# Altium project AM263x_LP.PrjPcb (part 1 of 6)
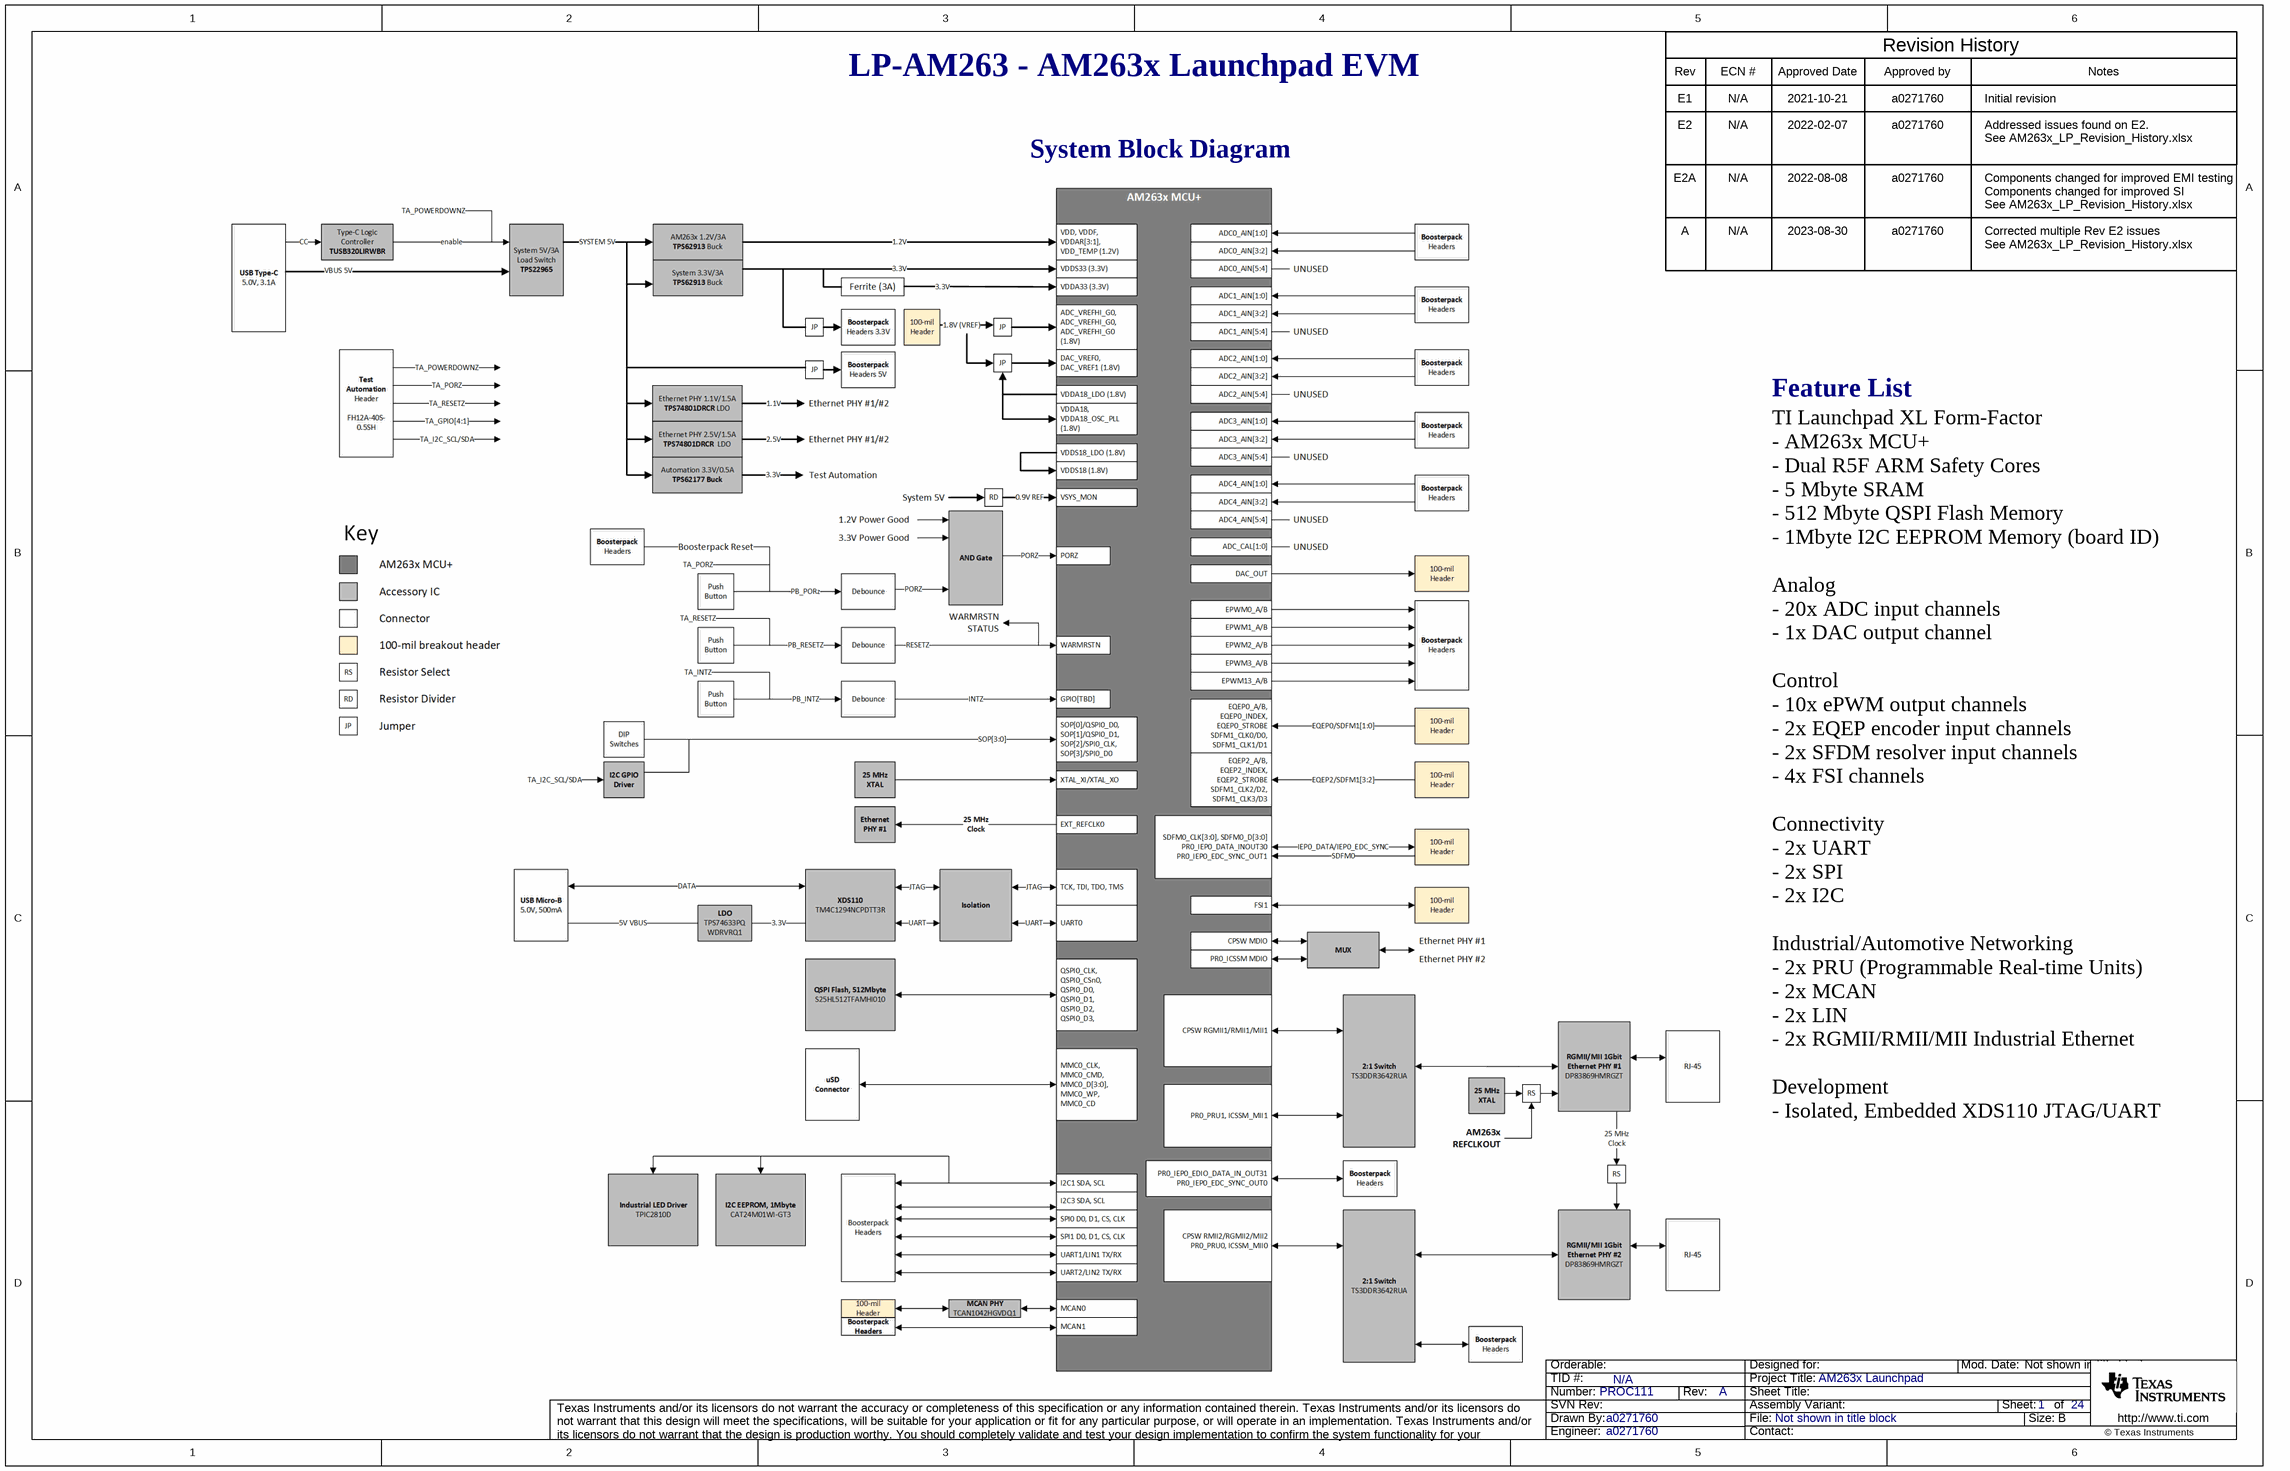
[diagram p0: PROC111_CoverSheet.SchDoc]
DrawnBy: a0271760; PCB_Rev: A; PRJ_Engineer: a0271760; PRJ_Number: PROC111; PRJ_Title: AM263x Launchpad; Sch_Rev: A; TID: N/A
24 sheets, 815 parts. Net scope: global (net labels, ports and power ports of the same name join across sheets).
Board file: PROC111A.PcbDoc
Sheets:
  PROC111_CoverSheet.SchDoc
  PROC111_System_Power_1.SchDoc
  PROC111_System_Power_2.SchDoc
  PROC111_AM263x_1_Power.SchDoc
  PROC111_AM263x_2_Clock_Reset_Boot_JTAG.SchDoc
  PROC111_AM263x_Serial_Connectivity.SchDoc
  PROC111_AM263x_3_QSPI_MMC.SchDoc
  PROC111_AM263x_4_ADC_DAC.SchDoc
  PROC111_AM263x_5_ePWM_eQEP_FSI.SchDoc
  PROC111_AM263x_6_RGMII_MII.SchDoc
  PROC111_AM263x_7_PRU.SchDoc
  PROC111_AM263x_8_SDFM.SchDoc
  PROC111_Push_Buttons.SchDoc
  PROC111_Test_Automation.SchDoc
  PROC111_Ehernet_PHY_1.SchDoc
  PROC111_Ehernet_PHY_2.SchDoc
  PROC111_Ehernet_RJ45_1.SchDoc
  PROC111_Ehernet_RJ45_2.SchDoc
  PROC111_Boosterpack_Headers.SchDoc
  PROC111_Breakout_Headers.SchDoc
  PROC111_XDS110_1.SchDoc
  PROC111_XDS110_2.SchDoc
  PROC111_LED.SchDoc
  PROC111_Hardware.SchDoc

## Sheet PROC111_CoverSheet.SchDoc
size 431 x 279 mm; Date: Not shown in title block; ApprovedBy: Not shown in title block; CheckedBy: Not shown in title block; Author: Not shown in title block; CompanyName: Not shown in title block; Engineer: Not shown in title block; Organization: Not shown in title block; Address1: Not shown in title block; Address2: Not shown in title block; Address3: Not shown in title block; Address4: Not shown in title block; DocumentNumber: 1; Revision: Use project parameter SCH_Rev; SheetNumber: 1; SheetTotal: 24; PageSetup: Record=PageOptions¦CenterHorizontal=True¦CenterVertical=True¦PrintScale=1.00¦XCorrection=1.00¦YCorrection=1.00¦PrintKind=0¦BorderSize=5000000¦LeftOffset=0¦BottomOffset=0¦Orientation=2¦PaperLength=1000¦PaperWidth=1000¦Scale=100¦PaperSource=15¦PrintQuality=600¦MediaType=1¦DitherType=10¦PaperKind=Letter¦PrintScaleMode=1

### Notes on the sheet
- LP-AM263 - AM263x Launchpad EVM
- Rev
- E1
- ECN #
- N/A
- Approved Date
- 2021-10-21
- Approved by
- a0271760
- Revision History
- Initial revision
- Notes
- System Block Diagram
- E2
- 2022-02-07
- Addressed issues found on E2.
- See AM263x_LP_Revision_History.xlsx
- E2A
- A
- 2022-08-08
- 2023-08-30
- Components changed for improved SI
- Components changed for improved EMI testing
- Corrected multiple Rev E2 issues
- Feature List
- TI Launchpad XL Form-Factor
  - AM263x MCU+
  - Dual R5F ARM Safety Cores
  - 5 Mbyte SRAM
  - 512 Mbyte QSPI Flash Memory
  - 1Mbyte I2C EEPROM Memory (board ID)
  Analog
  - 20x ADC input channels
  - 1x DAC output channel
  Control
  - 10x ePWM output channels
  - 2x EQEP encoder input channels
  - 2x SFDM resolver input channels
  - 4x FSI channels
  Connectivity
  - 2x UART
  - 2x SPI
  - 2x I2C
  Industrial/Automotive Networking
  - 2x PRU (Programmable Real-time Units)
  - 2x MCAN
  - 2x LIN
  - 2x RGMII/RMII/MII Industrial Ethernet
  Development
  - Isolated, Embedded XDS110 JTAG/UART

## Sheet PROC111_System_Power_1.SchDoc
size 431 x 279 mm; Date: Not shown in title block; ApprovedBy: Not shown in title block; CheckedBy: Not shown in title block; Author: Not shown in title block; CompanyName: Not shown in title block; Engineer: Not shown in title block; Organization: Not shown in title block; Address1: Not shown in title block; Address2: Not shown in title block; Address3: Not shown in title block; Address4: Not shown in title block; DocumentNumber: 2; Revision: Use project parameter SCH_Rev; SheetNumber: 2; SheetTotal: 24; PageSetup: Record=PageOptions¦CenterHorizontal=True¦CenterVertical=True¦PrintScale=1.00¦XCorrection=1.00¦YCorrection=1.00¦PrintKind=0¦BorderSize=5000000¦LeftOffset=0¦BottomOffset=0¦Orientation=2¦PaperLength=1000¦PaperWidth=1000¦Scale=100¦PaperSource=15¦PrintQuality=600¦MediaType=1¦DitherType=10¦PaperKind=Letter¦PrintScaleMode=1
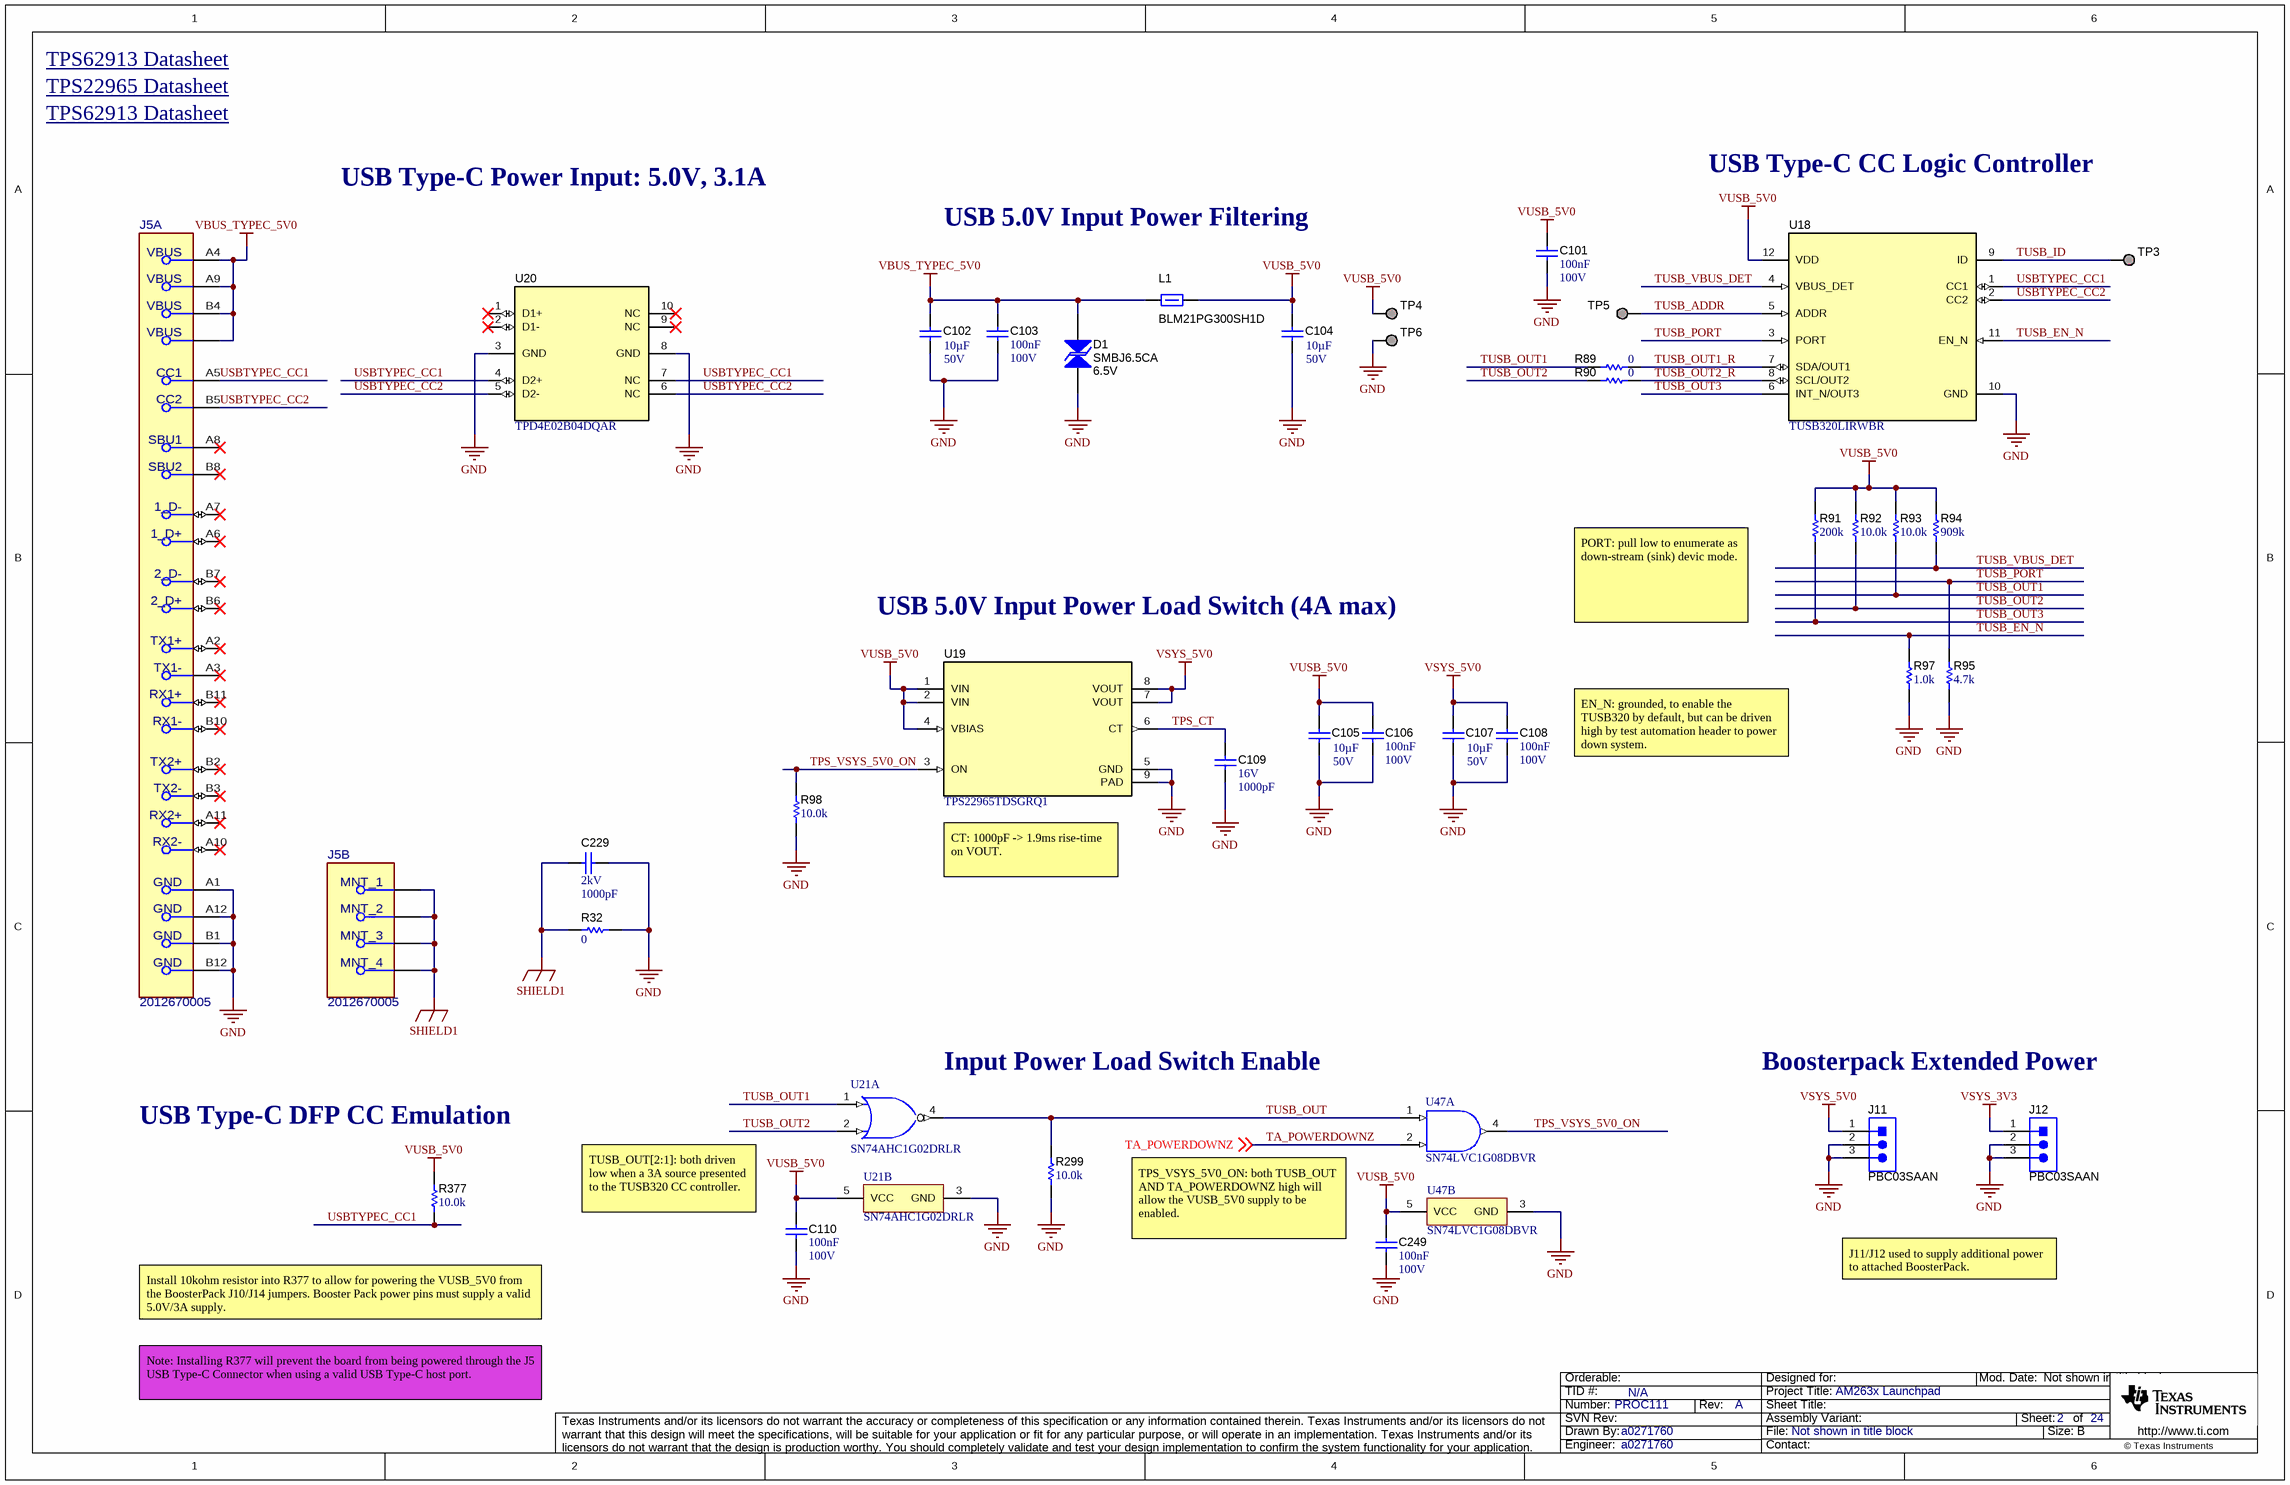
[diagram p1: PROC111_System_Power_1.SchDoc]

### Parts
C101  Cap_F: 100nF  VDC_V: 100V  [0603]  (hidden comment: GRM188R72A104KA35D)
C102  VDC_V: 50V  ValueDisplayed: 10µF  [1210_270]  (hidden comment: CL32A106KBJNNNE)
C103  Cap_F: 100nF  VDC_V: 100V  [0603]  (hidden comment: GRM188R72A104KA35J)
C104  VDC_V: 50V  ValueDisplayed: 10µF  [1210_270]  (hidden comment: CL32A106KBJNNNE)
C105  VDC_V: 50V  ValueDisplayed: 10µF  [1210_270]  (hidden comment: CL32A106KBJNNNE)
C106  Cap_F: 100nF  VDC_V: 100V  [0603]  (hidden comment: GRM188R72A104KA35D)
C107  VDC_V: 50V  ValueDisplayed: 10µF  [1210_270]  (hidden comment: CL32A106KBJNNNE)
C108  Cap_F: 100nF  VDC_V: 100V  [0603]  (hidden comment: GRM188R72A104KA35D)
C109  VDC_V: 16V  ValueDisplayed: 1000pF  [0402]  (hidden comment: GRM155R71C102KA01D)
C110  Cap_F: 100nF  VDC_V: 100V  [0603]  (hidden comment: GRM188R72A104KA35D)
C229  VDC_V: 2kV  ValueDisplayed: 1000pF  [1808]  (hidden comment: GR442QR73D102KW01L)
C249  Cap_F: 100nF  VDC_V: 100V  [0603]  (hidden comment: GRM188R72A104KA35D)
D1  SMBJ6.5CA  value 6.5V  [SMB-Bi]
J5  2012670005  [FP-2012670005_CONN_USB_9MM39_8MM21-MFG]  (parts A,B of 2)
J11  PBC03SAAN  [PBC03SAAN]
J12  PBC03SAAN  [PBC03SAAN]
L1  BLM21PG300SH1D  [0805_HV]
R32  ValueDisplayed: 0  [0805_HV]  (hidden comment: ERJ-6GEY0R00V)
R89  ValueDisplayed: 0  [0402L]  (hidden comment: ERJ-2GE0R00X)
R90  ValueDisplayed: 0  [0402L]  (hidden comment: ERJ-2GE0R00X)
R91  ValueDisplayed: 200k  [0402]  (hidden comment: CRCW0402200KJNED)
R92  ValueDisplayed: 10.0k  [0402]  (hidden comment: ERJ-2RKF1002X)
R93  ValueDisplayed: 10.0k  [0402]  (hidden comment: ERJ-2RKF1002X)
R94  ValueDisplayed: 909k  [0402]  (hidden comment: CRCW0402909KFKED)
R95  ValueDisplayed: 4.7k  [0402]  (hidden comment: CRCW04024K70JNED)
R97  ValueDisplayed: 1.0k  [0402]  (hidden comment: ERJ-2GEJ102X)
R98  ValueDisplayed: 10.0k  [0402]  (hidden comment: ERJ-2RKF1002X)
R299  ValueDisplayed: 10.0k  [0402]  (hidden comment: ERJ-2RKF1002X)
R377  ValueDisplayed: 10.0k  [0402]  (hidden comment: ERJ-2RKF1002X)
TP3  TESTPOINT  [TP_25MIL-SMT]  (value not drawn)  (no BOM)
TP4  TESTPOINT  [TP_25MIL-SMT]  (value not drawn)  (no BOM)
TP5  TESTPOINT  [TP_25MIL-SMT]  (value not drawn)  (no BOM)
TP6  TESTPOINT  [TP_25MIL-SMT]  (value not drawn)  (no BOM)
U18  TUSB320LIRWBR  [RWB0012A]
U19  TPS22965TDSGRQ1  [DSG0008B]
U20  TPD4E02B04DQAR  [DQA0010A]
U21  SN74AHC1G02DRLR  [DRL0005A]  (parts A,B of 2)
U47  SN74LVC1G08DBVR  [DBV0005A_N]  (parts A,B of 2)

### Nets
GND: C101.2 C102.2 C103.2 C104.2 C105.2 C106.2 C107.2 C108.2 C109.2 C110.2 C229.1 C249.2 D1.1 J5.A1(GND) J5.A12(GND) J5.B1(GND) J5.B12(GND) J11.2 J11.3 J12.2 J12.3 R32.2 R95.1 R97.1 R98.2 R299.2 TP6.1 U18.10(GND) U19.5(GND) U19.9(PAD) U20.3(GND) U20.8(GND) U21.3(GND) U47.3(GND)
SHIELD1: C229.2 J5.1(MNT_1) J5.2(MNT_2) J5.3(MNT_3) J5.4(MNT_4) R32.1
VBUS_TYPEC_5V0: C102.1 C103.1 D1.2 J5.A4(VBUS) J5.A9(VBUS) J5.B4(VBUS) J5.B9(VBUS) L1.1
VSYS_3V3: J12.1
VSYS_5V0: C107.1 C108.1 J11.1 U19.7(VOUT) U19.8(VOUT)
VUSB_5V0: C101.1 C104.1 C105.1 C106.1 C110.1 C249.1 L1.2 R91.2 R92.1 R93.1 R94.2 R377.1 TP4.1 U18.12(VDD) U19.1(VIN) U19.2(VIN) U19.4(VBIAS) U21.5(VCC) U47.5(VCC)
TA_POWERDOWNZ: U47.2(B) ; off-sheet TA_POWERDOWNZ
TPS_CT: C109.1 U19.6(CT)
TPS_VSYS_5V0_ON: R98.1 U19.3(ON) U47.4(Y)
TUSB_ADDR: TP5.1 U18.5(ADDR)
TUSB_EN_N: R97.2 U18.11(EN_N)
TUSB_ID: TP3.1 U18.9(ID)
TUSB_OUT: R299.1 U21.4(Y) U47.1(A)
TUSB_OUT1: R89.2 R93.2 U21.1(A)
TUSB_OUT1_R: R89.1 U18.7(SDA/OUT1)
TUSB_OUT2: R90.2 R92.2 U21.2(B)
TUSB_OUT2_R: R90.1 U18.8(SCL/OUT2)
TUSB_OUT3: R91.1 U18.6(INT_N/OUT3)
TUSB_PORT: R95.2 U18.3(PORT)
TUSB_VBUS_DET: R94.1 U18.4(VBUS_DET)
USBTYPEC_CC1: J5.A5(CC1) R377.2 U18.1(CC1) U20.4(D2+) U20.7(NC)
USBTYPEC_CC2: J5.B5(CC2) U18.2(CC2) U20.5(D2-) U20.6(NC)

Not connected (* = marked no-connect by the designer): J5 A2(TX1+)* A3(TX1-)* A6(1_D+)* A7(1_D-)* A8(SBU1)* A10(RX2-)* A11(RX2+)* B2(TX2+)* B3(TX2-)* B6(2_D+)* B7(2_D-)* B8(SBU2)* B10(RX1-)* B11(RX1+)*; U20 1(D1+)* 2(D1-)* 9(NC)* 10(NC)*

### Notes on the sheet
- TPS62913 Datasheet <https://www.ti.com/product/TPS62913>
- TPS22965 Datasheet <http://www.ti.com/lit/ds/symlink/tps22965-q1.pdf>
- TPS62913 Datasheet <datasheets/IC-TPS62913RPUR.pdf>
- USB Type-C Power Input: 5.0V, 3.1A
- USB 5.0V Input Power Filtering
- USB Type-C CC Logic Controller
- USB 5.0V Input Power Load Switch (4A max)
- PORT: pull low to enumerate as down-stream (sink) devic mode.
- EN_N: grounded, to enable the TUSB320 by default, but can be driven high by test automation header to power down system.
  TA_POWERDOWNZ: pulled high by default. Can be driven low by TA Header to disable USB 5.0V supply.
- (near U19) CT: 1000pF -> 1.9ms rise-time on VOUT.
- (near U21) Input Power Load Switch Enable
- Boosterpack Extended Power
- USB Type-C DFP CC Emulation
- (near C110) TUSB_OUT[2:1]: both driven low when a 3A source presented to the TUSB320 CC controller.
- (near C249) TPS_VSYS_5V0_ON: both TUSB_OUT AND TA_POWERDOWNZ high will allow the VUSB_5V0 supply to be enabled.
- J11/J12 used to supply additional power to attached BoosterPack.
- Install 10kohm resistor into R377 to allow for powering the VUSB_5V0 from the BoosterPack J10/J14 jumpers. Booster Pack power pins must supply a valid 5.0V/3A supply.
- Note: Installing R377 will prevent the board from being powered through the J5 USB Type-C Connector when using a valid USB Type-C host port.

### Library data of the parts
C101 C106 C108 C110 C249 = CMP-0007469-4: CAP, CERM, 0.1 uF, 100 V, +/- 10%, X7R, 0603; Manufacturer: MuRata; TaMin_C: -55°C; Polarized: N; SizeAreaWB_mm2: 4.68; Value1: Unknown; U/M: EA; Value: 0.1uF; TaMax_C: 125°C; SizeZ_mm: 1; SizeX_mm: 1.6; SizeY_mm: 0.8; SizeArea_mm2: 1.28; AEC Category: Q200
C102 C104 C105 C107 = CMP-0079200-1: CAP, CERM, 10 µF, 50 V,+/- 10%, X5R, 1210; Manufacturer: Samsung Electro-Mechanics; TaMin_C: -55°C; ESR_ohm: 5m; Polarized: N; SizeAreaWB_mm2: 14.7; Value1: 0.005 ohm; U/M: EA; Value: 10uF; TaMax_C: 85°C; SizeZ_mm: 2.7; SizeX_mm: 3.2; SizeY_mm: 2.5; Cap_Case: 1210; SizeArea_mm2: 8; AEC Category: Q200
C103 = CMP-0007470-5: CAP, CERM, 0.1 uF, 100 V, +/- 10%, X7R, 0603; Manufacturer: MuRata; TaMin_C: -55°C; Polarized: N; SizeAreaWB_mm2: 4.68; Value1: Unknown; U/M: EA; Value: 0.1uF; TaMax_C: 125°C; SizeZ_mm: 1; SizeX_mm: 1.6; SizeY_mm: 0.8; SizeArea_mm2: 1.28; AEC Category: Q200
C109 = CMP-0006638-1: CAP, CERM, 1000 pF, 16 V, +/- 10%, X7R, 0402; Manufacturer: MuRata; TaMin_C: -55°C; Polarized: N; SizeAreaWB_mm2: 3; Value1: Unknown; U/M: EA; Value: 1000pF; TaMax_C: 125°C; SizeZ_mm: 0.6; SizeX_mm: 1; SizeY_mm: 0.5; Cap_F: 1nF; AEC Category: Q200
C229 = CMP-0009436-2: CAP, CERM, 1000 pF, 2000 V, +/- 10%, X7R, 1808; Manufacturer: MuRata; TaMin_C: -55°C; Polarized: N; SizeAreaWB_mm2: 16.5; Value1: Unknown; U/M: EA; Value: 1000pF; TaMax_C: 125°C; SizeZ_mm: 2.03; SizeX_mm: 4.5; SizeY_mm: 2; Value2: 2000V; SizeArea_mm2: 9; Cap_F: 1nF; AEC Category: Q200
D1 = CMP-0005599-2: Diode, TVS, Bi, 6.5 V, SMB; Manufacturer: Littelfuse; SizeZ_mm: 2.6; SizeY_mm: 3.81; Ppk: 600W; AEC Category: Q101; RJA_CperW: 100; SizeArea_mm2: 21.336; SizeX_mm: 5.6; SizeAreaWB_mm2: 44.156
J5 = CMP-0093552-1: USB-C (USB TYPE-C) USB 3.2 Gen 2 (USB 3.1 Gen 2, Superspeed + (USB 3.1)) Receptacle Connector 24 Position Surface Mount, Right Angle; Through Hole; Manufacturer: Molex; Voltage_V: 30V; SizeZ_mm: 3.86mm; DUT-Pitch_mm: 0.5mm; Shrouded: true; ContactFinish: Gold,Nickel; Usb Standard: USB 3.1; AEC Qualified: No; Is Female: yes
J11 J12 = CMP-0002334-1: Header, 100mil, 3x1, Gold, TH; Manufacturer: Sullins Connector Solutions; CNHeader: TRUE; Green_Lifecycle: Not Set; Green_REACh: Incomplete; CT: FALSE
L1 = CMP-0003364-1: Ferrite Bead, 30 ohm @ 100 MHz, 4 A, 0805; Manufacturer: MuRata; ZTyp@100MHz_Ohm: 30; SizeAreaWB_mm2: 6.75; DCR_ohm: 14m; Value1: 0.014 ohm; Value: 30 ohm; Imax_A: 4A; SizeZ_mm: 1.45; SizeX_mm: 2; SizeY_mm: 1.25; SizeArea_mm2: 2.5
R32 = CMP-0020616-3: RES, 0, 5%, 0.125 W, AEC-Q200 Grade 0, 0805; Manufacturer: Panasonic; Power_W: 125mW; TempCo: 600 ppm/C; Value_Code: 0000; Value: 0; EIA_Code: E24; SizeX_mm: 2; SizeY_mm: 1.25; SizeZ_mm: 1.45; Value2: 0.125W; SizeArea_mm2: 2.5; AEC Qualified: Y; VDC_V: 150V; AEC Category: Q200; SizeAreaWB_mm2: 6.75
R89 R90 = CMP-0026992-3: RES, 0, 5%, 0.1 W, AEC-Q200 Grade 0, 0402; Manufacturer: Panasonic; Power_W: 100mW; TempCo: 600 ppm/C; Value_Code: 0000; Value: 0; EIA_Code: E24; SizeX_mm: 1; SizeY_mm: 0.5; SizeZ_mm: 0.6; Value2: 0.1W; AEC Qualified: Y; VDC_V: 50V; AEC Category: Q200; SizeAreaWB_mm2: 3
R91 = CMP-0026873-2: RES, 200 k, 5%, 0.063 W, AEC-Q200 Grade 0, 0402; Manufacturer: Vishay-Dale; Power_W: 63mW; TempCo: 200 ppm/C; Value: 200k; EIA_Code: E24; SizeX_mm: 1; SizeY_mm: 0.5; SizeZ_mm: 0.6; Value2: 0.063W; AEC Qualified: Y; VDC_V: 50V; AEC Category: Q200; AEC Grade: 0
R92 R93 R98 R299 R377 = CMP-0026658-1: RES, 10.0 k, 1%, 0.1 W, 0402; Manufacturer: Panasonic; Power_W: 100mW; TempCo: 100 ppm/C; Value_Code: 10k0; U/M: EA; Value: 10.0k; EIA_Code: E96; Res_ohm: 10k; SizeX_mm: 1; SizeY_mm: 0.5; SizeZ_mm: 0.6; Value2: 0.1W; VDC_V: 50V; AEC Category: Q200
R94 = CMP-0026603-2: RES, 909 k, 1%, 0.063 W, AEC-Q200 Grade 0, 0402; Manufacturer: Vishay-Dale; Power_W: 63mW; TempCo: 100 ppm/C; Value: 909k; EIA_Code: E96; SizeX_mm: 1; SizeY_mm: 0.5; SizeZ_mm: 0.6; Value2: 0.063W; AEC Qualified: Y; VDC_V: 50V; AEC Category: Q200; AEC Grade: 0
R95 = CMP-0026938-5: RES, 4.7 k, 5%, 0.063 W, AEC-Q200 Grade 0, 0402; Manufacturer: Vishay-Dale; Power_W: 63mW; TempCo: 200 ppm/C; Value_Code: 4k70; Value: 4.7k; EIA_Code: E24; SizeX_mm: 1; SizeY_mm: 0.5; SizeZ_mm: 0.6; Value2: 0.063W; AEC Qualified: Y; VDC_V: 50V; AEC Category: Q200; AEC Grade: 0
R97 = CMP-0078193-1: RES, 1.0 k, 5%, 0.1 W, AEC-Q200 Grade 0, 0402; Manufacturer: Panasonic; Value_Code: 1k00; SizeArea_mm2: 0.5; AEC Qualified: Y; AEC Category: Q200; Res_ohm: 1k; Value: 1.0k; SizeZ_mm: 0.6; Green_REACh: Passed; EIA_Code: E24; TempCo: 200 ppm/C; AEC Grade: 0; Power_W: 100mW; VDC_V: 50V; Value2: 0.1W; Green_Lifecycle: Active; U/M: EA; SizeX_mm: 1
TP3-TP6 = CMP-0078143-3: TEST POINT.  No entry in BOM.
U18 = CMP-0073635-2: USB Type-C Configuration Channel Logic and Port Control, RWB0012A (X2QFN-12); Alternate Manufacturer: Texas Instruments; SizeAreaWB_mm2: 6.76; SizeZ_mm: 0.4; SizeX_mm: 1.6; SizeArea_mm2: 2.56; CompType: IC; AEC Category: Q200; AEC Qualified: N; Rating: Catalog
U19 = CMP-0073678-3: 5.5V, 4A, 16mΩ Automotive Load Switch With Adjustable Rise Time and Optional Quick Output Discharge, DSG0008B (WSON-8); Alternate PartNumber: TPS22965TDSGTQ1; Alternate Manufacturer: Texas Instruments; Green_Lifecycle: Active; SizeAreaWB_mm2: 9.0; Green_REACh: Passed; U/M: EA; SizeZ_mm: 0.8; SizeX_mm: 2.0; SizeArea_mm2: 4.0; CompType: IC; AEC Category: Q200; AEC Qualified: Y
U20 = CMP-0073612-3: 4-Channel ESD Protection Diode for USB Type-C and HDMI 2.0, DQA0010A (USON-10); Alternate Manufacturer: Texas Instruments; Green_Lifecycle: Active; SizeAreaWB_mm2: 7.0; Green_REACh: Passed; SizeZ_mm: 0.55; SizeX_mm: 1.0; SizeY_mm: 2.5; CompType: IC; AEC Category: Q200; AEC Qualified: Y
U21 = CMP-0051530-2: Single 2-Input Positive-NOR Gate, DRL0005A, LARGE T&R; Manufacturer: Texas Instruments; Schmitt Trigger: No; Technology Family: AHC; Logic: True; Gate Type: NOR; Output Type: CMOS; Sub-Family: NAND Gate; Rating: Catalog; F @ Nom Voltage(Max)(Mhz): 75; ICC @ Nom Voltage(Max)(mA): 0.01; tpd @ Nom Voltage(Max)(ns): 11.4,7.5; Voltage(Nom)(V): 3.3,5; Output Drive (IOL/IOH)(Max)(mA): 50/-50; VCC(Max)(V): 5.5; VCC(Min)(V): 2; Bits(#): 1; AEC Category: Q200; AEC Qualified: N; CompType: IC; SizeArea_mm2: 2.56; SizeX_mm: 1.6; SizeZ_mm: 0.6
U47 = CMP-0051588-2: Single 2-Input Positive-AND Gate, DBV0005A, LARGE T&R; Manufacturer: Texas Instruments; Logic: True; ICC @ Nom Voltage(Max)(mA): 0.01; VCC(Min)(V): 1.65; Bits(#): 1; Rating: Catalog; Schmitt Trigger: No; Voltage(Nom)(V): 1.8,2.5,3.3,5; Output Drive (IOL/IOH)(Max)(mA): 32/-32; Gate Type: AND; tpd @ Nom Voltage(Max)(ns): 4.5,6,4,5; VCC(Max)(V): 5.5; Output Type: CMOS; F @ Nom Voltage(Max)(Mhz): 150; Input Type: CMOS/TTL; Technology Family: LVC; AEC Category: Q200; AEC Qualified: N; CompType: IC

## Sheet PROC111_System_Power_2.SchDoc
size 431 x 279 mm; Date: Not shown in title block; ApprovedBy: Not shown in title block; CheckedBy: Not shown in title block; Author: Not shown in title block; CompanyName: Not shown in title block; Engineer: Not shown in title block; Organization: Not shown in title block; Address1: Not shown in title block; Address2: Not shown in title block; Address3: Not shown in title block; Address4: Not shown in title block; DocumentNumber: 3; Revision: Use project parameter SCH_Rev; SheetNumber: 3; SheetTotal: 24; PageSetup: Record=PageOptions¦CenterHorizontal=True¦CenterVertical=True¦PrintScale=1.00¦XCorrection=1.00¦YCorrection=1.00¦PrintKind=0¦BorderSize=5000000¦LeftOffset=0¦BottomOffset=0¦Orientation=2¦PaperLength=1000¦PaperWidth=1000¦Scale=100¦PaperSource=15¦PrintQuality=600¦MediaType=1¦DitherType=10¦PaperKind=Letter¦PrintScaleMode=1
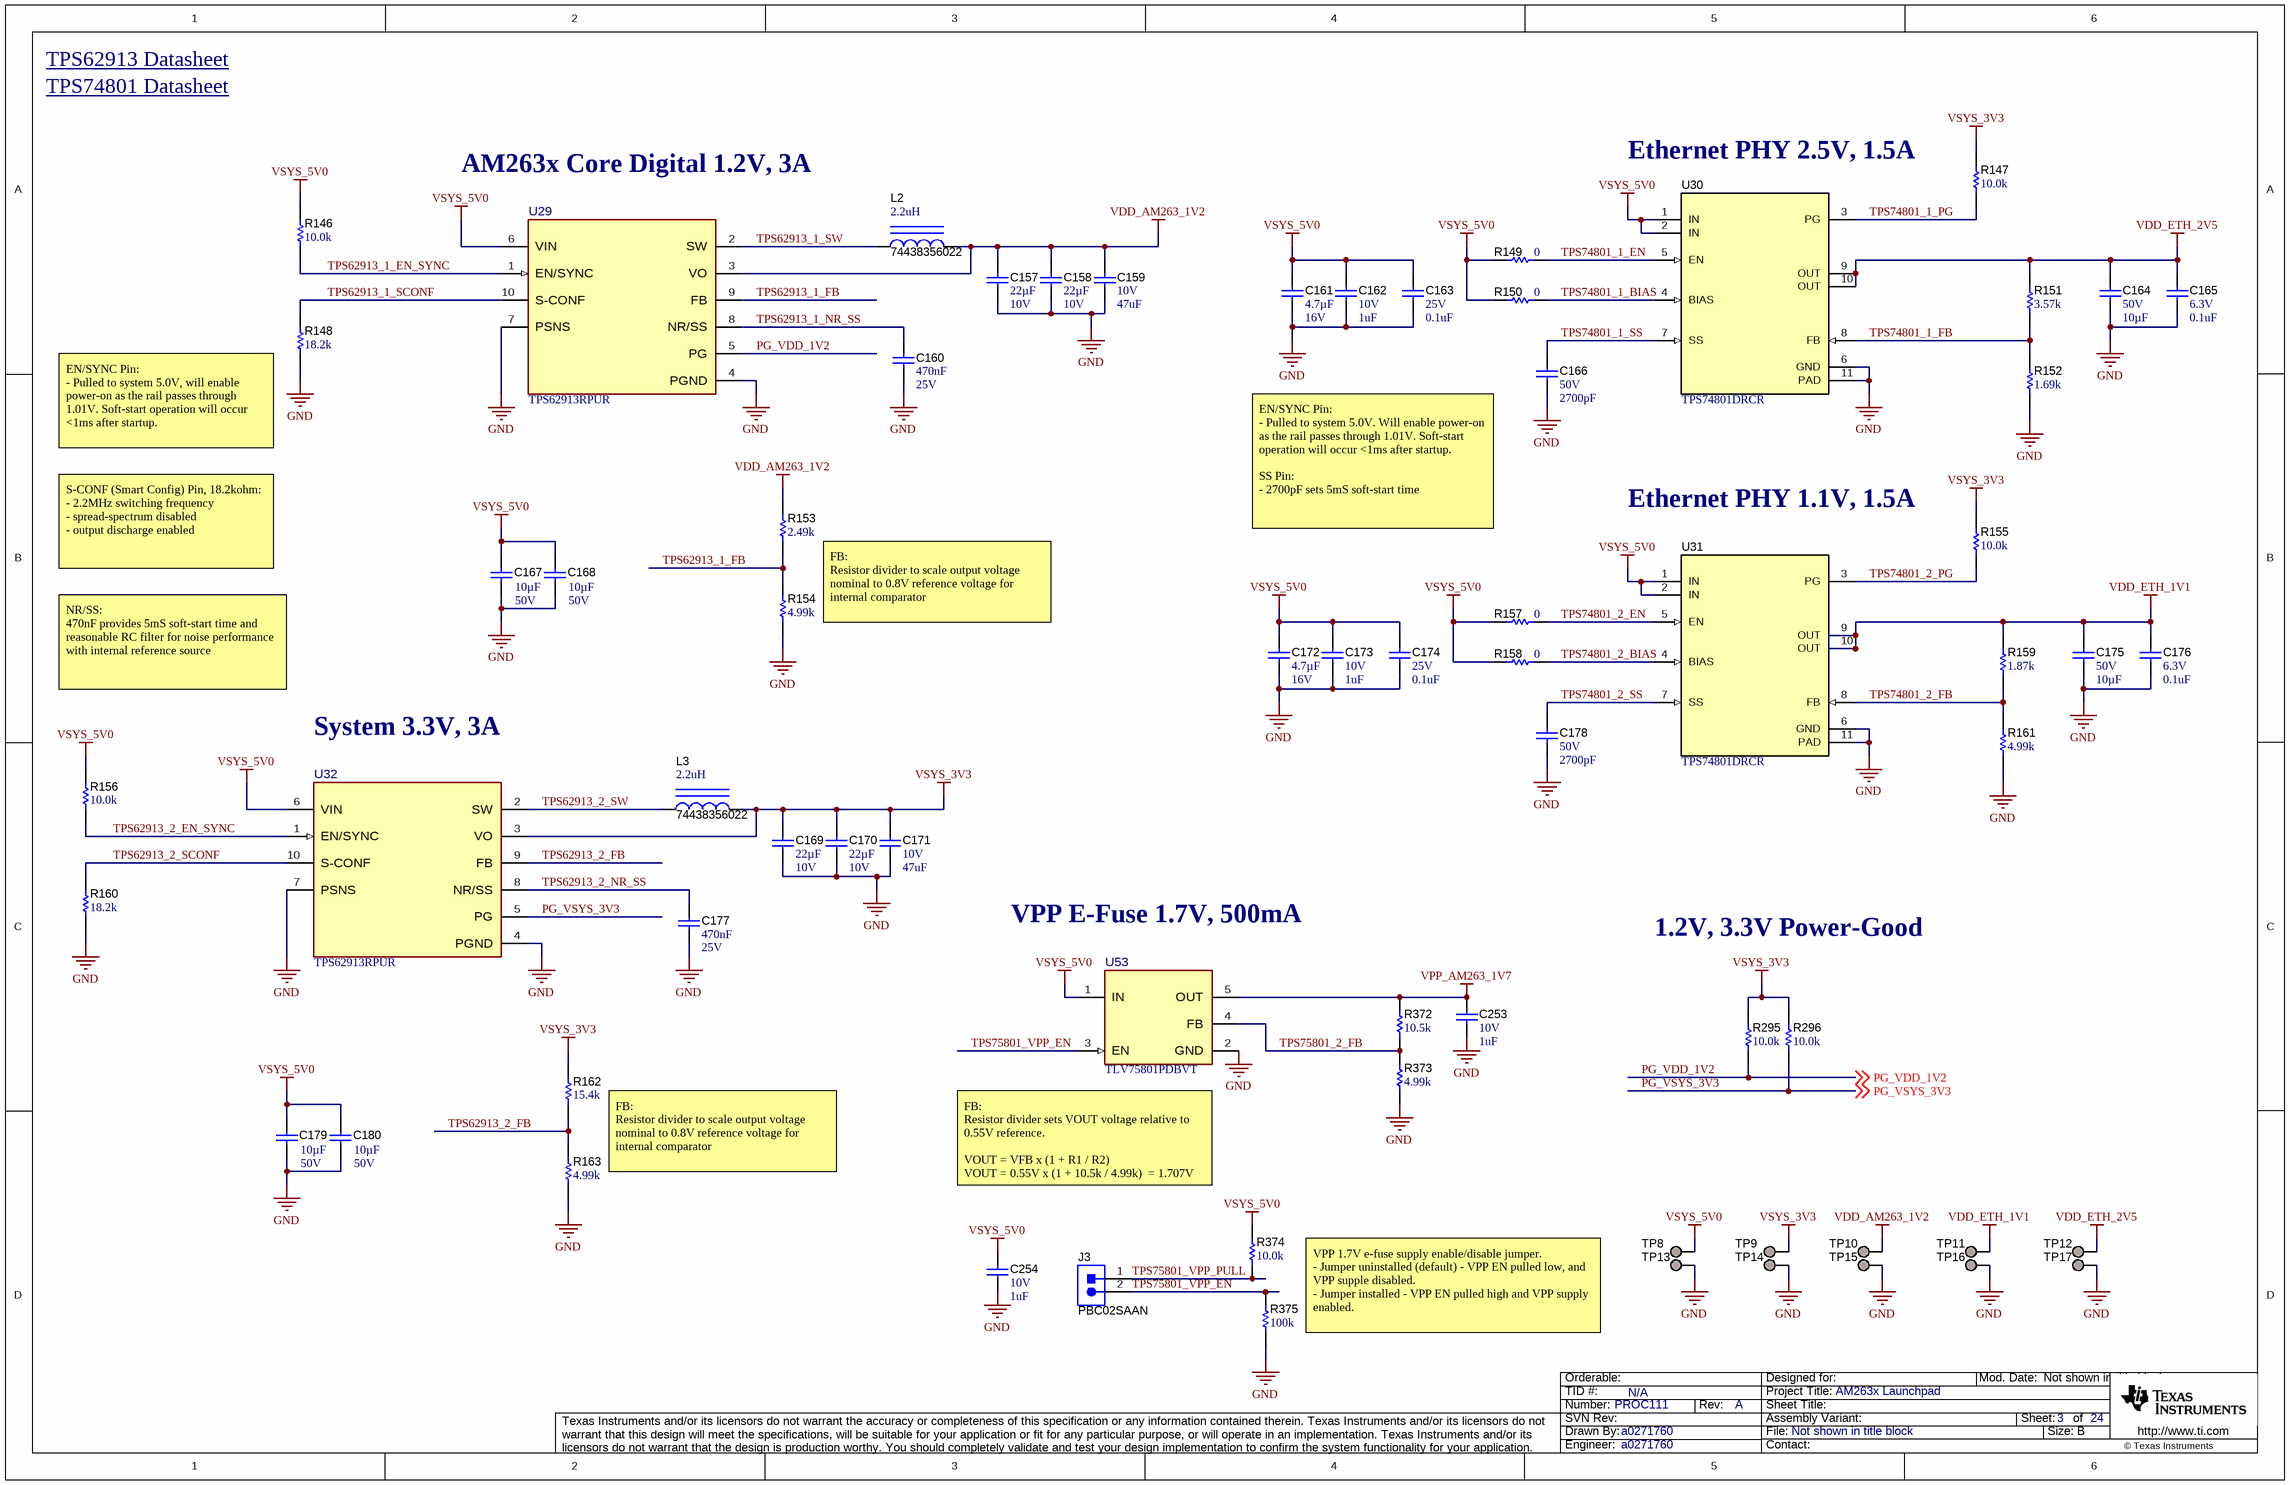
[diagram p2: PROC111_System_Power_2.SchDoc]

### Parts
C157  Cap_F: 22µF  VDC_V: 10V  [0805_HV]  (hidden comment: GRM21BZ71A226ME15L)
C158  Cap_F: 22µF  VDC_V: 10V  [0805_HV]  (hidden comment: GRM21BZ71A226ME15L)
C159  VDC_V: 10V  ValueDisplayed: 47uF  [1210_270]  (hidden comment: GRM32ER71A476ME15L)
C160  Cap_F: 470nF  VDC_V: 25V  [0603]  (hidden comment: GRM188R71E474KA12D)
C161  Cap_F: 4.7µF  VDC_V: 16V  [0603]  (hidden comment: GRM188Z71C475KE21D)
C162  VDC_V: 10V  ValueDisplayed: 1uF  [0402_070]  (hidden comment: GCM155C71A105KE38D)
C163  VDC_V: 25V  ValueDisplayed: 0.1uF  [0402]  (hidden comment: GRM155R71E104KE14D)
C164  VDC_V: 50V  ValueDisplayed: 10µF  [1210_270]  (hidden comment: CL32A106KBJNNNE)
C165  VDC_V: 6.3V  ValueDisplayed: 0.1uF  [0402]  (hidden comment: GRM155R70J104KA01D)
C166  VDC_V: 50V  ValueDisplayed: 2700pF  [0402]  (hidden comment: CL05B272KB5NNNC)
C167  VDC_V: 50V  ValueDisplayed: 10µF  [1210_270]  (hidden comment: CL32A106KBJNNNE)
C168  VDC_V: 50V  ValueDisplayed: 10µF  [1210_270]  (hidden comment: CL32A106KBJNNNE)
C169  Cap_F: 22µF  VDC_V: 10V  [0805_HV]  (hidden comment: GRM21BZ71A226ME15L)
C170  Cap_F: 22µF  VDC_V: 10V  [0805_HV]  (hidden comment: GRM21BZ71A226ME15L)
C171  VDC_V: 10V  ValueDisplayed: 47uF  [1210_270]  (hidden comment: GRM32ER71A476ME15L)
C172  Cap_F: 4.7µF  VDC_V: 16V  [0603]  (hidden comment: GRM188Z71C475KE21D)
C173  VDC_V: 10V  ValueDisplayed: 1uF  [0402_070]  (hidden comment: GCM155C71A105KE38D)
C174  VDC_V: 25V  ValueDisplayed: 0.1uF  [0402]  (hidden comment: GRM155R71E104KE14D)
C175  VDC_V: 50V  ValueDisplayed: 10µF  [1210_270]  (hidden comment: CL32A106KBJNNNE)
C176  VDC_V: 6.3V  ValueDisplayed: 0.1uF  [0402]  (hidden comment: GRM155R70J104KA01D)
C177  Cap_F: 470nF  VDC_V: 25V  [0603]  (hidden comment: GRM188R71E474KA12D)
C178  VDC_V: 50V  ValueDisplayed: 2700pF  [0402]  (hidden comment: CL05B272KB5NNNC)
C179  VDC_V: 50V  ValueDisplayed: 10µF  [1210_270]  (hidden comment: CL32A106KBJNNNE)
C180  VDC_V: 50V  ValueDisplayed: 10µF  [1210_270]  (hidden comment: CL32A106KBJNNNE)
C253  VDC_V: 10V  ValueDisplayed: 1uF  [0402_070]  (hidden comment: GCM155C71A105KE38D)
C254  VDC_V: 10V  ValueDisplayed: 1uF  [0402_070]  (hidden comment: GCM155C71A105KE38D)
J3  PBC02SAAN  [Sullins_PBC02SAAN]
L2  74438356022  ValueDisplayed: 2.2uH  [WE-MAPI_4020]
L3  74438356022  ValueDisplayed: 2.2uH  [WE-MAPI_4020]
R146  ValueDisplayed: 10.0k  [0402]  (hidden comment: ERJ-2RKF1002X)
R147  ValueDisplayed: 10.0k  [0402]  (hidden comment: ERJ-2RKF1002X)
R148  ValueDisplayed: 18.2k  [0805_HV]  (hidden comment: ERJ-6ENF1822V)
R149  ValueDisplayed: 0  [0402]  (hidden comment: ERJ-2GE0R00X)
R150  ValueDisplayed: 0  [0402]  (hidden comment: ERJ-2GE0R00X)
R151  ValueDisplayed: 3.57k  [0402]  (hidden comment: CRCW04023K57FKED)
R152  ValueDisplayed: 1.69k  [0402]  (hidden comment: CRCW04021K69FKED)
R153  ValueDisplayed: 2.49k  [0402]  (hidden comment: CRCW04022K49FKED)
R154  ValueDisplayed: 4.99k  [0402]  (hidden comment: CRCW04024K99FKED)
R155  ValueDisplayed: 10.0k  [0402]  (hidden comment: ERJ-2RKF1002X)
R156  ValueDisplayed: 10.0k  [0402]  (hidden comment: ERJ-2RKF1002X)
R157  ValueDisplayed: 0  [0402]  (hidden comment: ERJ-2GE0R00X)
R158  ValueDisplayed: 0  [0402]  (hidden comment: ERJ-2GE0R00X)
R159  ValueDisplayed: 1.87k  [0402]  (hidden comment: CRCW04021K87FKED)
R160  ValueDisplayed: 18.2k  [0805_HV]  (hidden comment: ERJ-6ENF1822V)
R161  ValueDisplayed: 4.99k  [0402]  (hidden comment: CRCW04024K99FKED)
R162  ValueDisplayed: 15.4k  [0402]  (hidden comment: CRCW040215K4FKED)
R163  ValueDisplayed: 4.99k  [0402]  (hidden comment: CRCW04024K99FKED)
R295  ValueDisplayed: 10.0k  [0402]  (hidden comment: ERJ-2RKF1002X)
R296  ValueDisplayed: 10.0k  [0402]  (hidden comment: ERJ-2RKF1002X)
R372  ValueDisplayed: 10.5k  [0402S]  (hidden comment: CRCW040210K5FKED)
R373  ValueDisplayed: 4.99k  [0402S]  (hidden comment: CRCW04024K99FKED)
R374  ValueDisplayed: 10.0k  [0402S]  (hidden comment: ERJ-2RKF1002X)
R375  ValueDisplayed: 100k  [0402]  (hidden comment: ERJ-2RKF1003X)
TP8  TESTPOINT  [TP_25MIL-SMT]  (value not drawn)  (no BOM)
TP9  TESTPOINT  [TP_25MIL-SMT]  (value not drawn)  (no BOM)
TP10  TESTPOINT  [TP_25MIL-SMT]  (value not drawn)  (no BOM)
TP11  TESTPOINT  [TP_25MIL-SMT]  (value not drawn)  (no BOM)
TP12  TESTPOINT  [TP_25MIL-SMT]  (value not drawn)  (no BOM)
TP13  TESTPOINT  [TP_25MIL-SMT]  (value not drawn)  (no BOM)
TP14  TESTPOINT  [TP_25MIL-SMT]  (value not drawn)  (no BOM)
TP15  TESTPOINT  [TP_25MIL-SMT]  (value not drawn)  (no BOM)
TP16  TESTPOINT  [TP_25MIL-SMT]  (value not drawn)  (no BOM)
TP17  TESTPOINT  [TP_25MIL-SMT]  (value not drawn)  (no BOM)
U29  TPS62913RPUR  [RPU0010A-MFG]
U30  TPS74801DRCR  [DRC0010J]
U31  TPS74801DRCR  [DRC0010J]
U32  TPS62913RPUR  [RPU0010A-MFG]
U53  TLV75801PDBVT  [DBV0005A-MFG]

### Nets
GND: C157.2 C158.2 C159.2 C160.2 C161.2 C162.2 C163.2 C164.2 C165.2 C166.2 C167.2 C168.2 C169.2 C170.2 C171.2 C172.2 C173.2 C174.2 C175.2 C176.2 C177.2 C178.2 C179.2 C180.2 C253.2 C254.2 R148.1 R152.1 R154.1 R160.1 R161.1 R163.1 R373.1 R375.1 TP13.1 TP14.1 TP15.1 TP16.1 TP17.1 U29.4(PGND) U29.7(PSNS) U30.6(GND) U30.11(PAD) U31.6(GND) U31.11(PAD) U32.4(PGND) U32.7(PSNS) U53.2(GND)
VDD_AM263_1V2: C157.1 C158.1 C159.1 L2.2 R153.2 TP10.1 U29.3(VO)
VDD_ETH_1V1: C175.1 C176.1 R159.2 TP11.1 U31.9(OUT) U31.10(OUT)
VDD_ETH_2V5: C164.1 C165.1 R151.2 TP12.1 U30.9(OUT) U30.10(OUT)
VPP_AM263_1V7: C253.1 R372.2 U53.5(OUT)
VSYS_3V3: C169.1 C170.1 C171.1 L3.2 R147.2 R155.2 R162.2 R295.2 R296.2 TP9.1 U32.3(VO)
VSYS_5V0: C161.1 C162.1 C163.1 C167.1 C168.1 C172.1 C173.1 C174.1 C179.1 C180.1 C254.1 R146.2 R149.1 R150.1 R156.2 R157.1 R158.1 R374.2 TP8.1 U29.6(VIN) U30.1(IN) U30.2(IN) U31.1(IN) U31.2(IN) U32.6(VIN) U53.1(IN)
PG_VDD_1V2: R295.1 U29.5(PG) ; off-sheet PG_VDD_1V2
PG_VSYS_3V3: R296.1 U32.5(PG) ; off-sheet PG_VSYS_3V3
TPS62913_1_EN_SYNC: R146.1 U29.1(EN/SYNC)
TPS62913_1_FB: R153.1 R154.2 U29.9(FB)
TPS62913_1_NR_SS: C160.1 U29.8(NR/SS)
TPS62913_1_SCONF: R148.2 U29.10(S-CONF)
TPS62913_1_SW: L2.1 U29.2(SW)
TPS62913_2_EN_SYNC: R156.1 U32.1(EN/SYNC)
TPS62913_2_FB: R162.1 R163.2 U32.9(FB)
TPS62913_2_NR_SS: C177.1 U32.8(NR/SS)
TPS62913_2_SCONF: R160.2 U32.10(S-CONF)
TPS62913_2_SW: L3.1 U32.2(SW)
TPS74801_1_BIAS: R150.2 U30.4(BIAS)
TPS74801_1_EN: R149.2 U30.5(EN)
TPS74801_1_FB: R151.1 R152.2 U30.8(FB)
TPS74801_1_PG: R147.1 U30.3(PG)
TPS74801_1_SS: C166.1 U30.7(SS)
TPS74801_2_BIAS: R158.2 U31.4(BIAS)
TPS74801_2_EN: R157.2 U31.5(EN)
TPS74801_2_FB: R159.1 R161.2 U31.8(FB)
TPS74801_2_PG: R155.1 U31.3(PG)
TPS74801_2_SS: C178.1 U31.7(SS)
TPS75801_2_FB: R372.1 R373.2 U53.4(FB)
TPS75801_VPP_EN: J3.2 R375.2 U53.3(EN)
TPS75801_VPP_PULL: J3.1 R374.1

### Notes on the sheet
- TPS74801 Datasheet <https://www.ti.com/store/ti/en/p/product/?p=TPS74801DRCR>
- TPS62913 Datasheet <https://www.ti.com/product/TPS62913>
- Ethernet PHY 2.5V, 1.5A
- AM263x Core Digital 1.2V, 3A
- (near R148) EN/SYNC Pin:
  - Pulled to system 5.0V, will enable power-on as the rail passes through 1.01V. Soft-start operation will occur <1ms after startup.
- S-CONF (Smart Config) Pin, 18.2kohm:
  - 2.2MHz switching frequency
  - spread-spectrum disabled
  - output discharge enabled
- EN/SYNC Pin:
  - Pulled to system 5.0V. Will enable power-on as the rail passes through 1.01V. Soft-start operation will occur <1ms after startup.
  SS Pin:
  - 2700pF sets 5mS soft-start time
- Ethernet PHY 1.1V, 1.5A
- FB:
  Resistor divider to scale output voltage nominal to 0.8V reference voltage for internal comparator
- NR/SS:
  470nF provides 5mS soft-start time and reasonable RC filter for noise performance with internal reference source
- System 3.3V, 3A
- VPP E-Fuse 1.7V, 500mA
- 1.2V, 3.3V Power-Good
- (near U53) FB:
  Resistor divider sets VOUT voltage relative to 0.55V reference.
  VOUT = VFB x (1 + R1 / R2)
  VOUT = 0.55V x (1 + 10.5k / 4.99k)  = 1.707V
- VPP 1.7V e-fuse supply enable/disable jumper.
  - Jumper uninstalled (default) - VPP EN pulled low, and VPP supple disabled.
  - Jumper installed - VPP EN pulled high and VPP supply enabled.

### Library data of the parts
C157 C158 C169 C170 = CMP-0008377-2: CAP, CERM, 22 uF, 10 V, +/- 20%, X7R, 0805; Manufacturer: MuRata; SizeY_mm: 1.25; Cap_Case: 0805; SizeArea_mm2: 2.5; AEC Qualified: N; AEC Category: Q200; ValueDisplayed: 22uF; TaMin_C: -55°C; SizeAreaWB_mm2: 6.75; Value1: Unknown; U/M: EA; Value: 22uF; TaMax_C: 125°C; SizeZ_mm: 1.45; SizeX_mm: 2
C159 C171 = CMP-0009221-2: CAP, CERM, 47 uF, 10 V, +/- 20%, X7R, 1210; Manufacturer: MuRata; TaMin_C: -55°C; Polarized: N; SizeAreaWB_mm2: 14.7; Value1: Unknown; U/M: EA; Value: 47uF; TaMax_C: 125°C; SizeZ_mm: 2.7; SizeX_mm: 3.2; SizeY_mm: 2.5; Cap_Case: 1210; SizeArea_mm2: 8; Cap_F: 47µF; AEC Category: Q200
C160 C177 = CMP-0007424-4: CAP, CERM, 0.47 uF, 25 V, +/- 10%, X7R, 0603; Manufacturer: MuRata; TaMin_C: -55°C; Polarized: N; SizeAreaWB_mm2: 4.68; Value1: Unknown; U/M: EA; Value: 0.47uF; TaMax_C: 125°C; SizeZ_mm: 1; SizeX_mm: 1.6; SizeY_mm: 0.8; SizeArea_mm2: 1.28; AEC Category: Q200
C161 C172 = CMP-0064936-4: CAP, CERM, 4.7 uF, 16 V,+/- 10%, X7R, 0603; Manufacturer: MuRata; TaMin_C: -55°C; Polarized: N; SizeAreaWB_mm2: 4.68; Value1: Unknown; U/M: EA; Value: 4.7uF; TaMax_C: 125°C; SizeZ_mm: 1; SizeX_mm: 1.6; SizeY_mm: 0.8; SizeArea_mm2: 1.28; AEC Category: Q200
C162 C173 C253 C254 = CMP-0006349-2: CAP, CERM, 1 uF, 10 V, +/- 10%, X7S, AEC-Q200 Grade 1, 0402; Manufacturer: MuRata; TaMin_C: -55°C; Polarized: N; SizeAreaWB_mm2: 3; Value1: Unknown; U/M: EA; Value: 1uF; TaMax_C: 125°C; SizeZ_mm: 0.7; SizeX_mm: 1; SizeY_mm: 0.5; Cap_Case: 0402; AEC Qualified: Y; Cap_F: 1µF; AEC Category: Q200
C163 C174 = CMP-0006659-2: CAP, CERM, 0.1 uF, 25 V, +/- 10%, X7R, 0402; Manufacturer: MuRata; TaMin_C: -55°C; Polarized: N; SizeAreaWB_mm2: 3; Value1: Unknown; U/M: EA; Value: 0.1uF; TaMax_C: 125°C; SizeZ_mm: 0.6; SizeX_mm: 1; SizeY_mm: 0.5; Cap_F: 100nF; AEC Category: Q200
C164 C167 C168 C175 C179 C180 = CMP-0079200-1: as C102 on sheet PROC111_System_Power_1
C165 C176 = CMP-0006623-2: CAP, CERM, 0.1 uF, 6.3 V, +/- 10%, X7R, 0402; Manufacturer: MuRata; TaMin_C: -55°C; Polarized: N; SizeAreaWB_mm2: 3; Value1: Unknown; U/M: EA; Value: 0.1uF; TaMax_C: 125°C; SizeZ_mm: 0.6; SizeX_mm: 1; SizeY_mm: 0.5; Cap_F: 100nF; AEC Category: Q200
C166 C178 = CMP-0860564-1: CAP, CERM, 2700 pF, 50 V,+/- 10%, X7R, 0402; Manufacturer: Samsung Electro-Mechanics; TaMin_C: -55°C; Polarized: N; SizeAreaWB_mm2: 3; U/M: EA; Value: 2700pF; TaMax_C: 125°C; SizeZ_mm: 0.6; SizeX_mm: 1; SizeY_mm: 0.5; Cap_F: 2.7nF; AEC Category: Q200
J3 = CMP-0054566-1: Header, 100mil, 2x1, Gold, TH; Manufacturer: Sullins Connector Solutions; CNHeader: TRUE; Current_A: 3A; Green_Lifecycle: Active; Shrouded: N; Gender: Male; Green_REACh: Passed; Voltage_V: 1.8kV; Row_Count: 1; Pitch_mm: 2.54; CT: FALSE; Cert_UL: Y
L2 L3 = CMP-0064169-1: Inductor, Shielded, 2.2 uH, 4.7 A, 0.029 ohm, SMD; Manufacturer: Wurth Elektronik; Isat: 6.2A @ 20% inductance drop; Irms: 4.7A @ 40C rise; Green_Lifecycle: Active; SizeAreaWB_mm2: 26.01; DCR_ohm: 29m; Green_REACh: Passed; Value: 2.2uH; Imax_A: 4.7A; SizeZ_mm: 2.1; SizeX_mm: 4.1; SizeArea_mm2: 16.81; Ind_H: 2.2µH; AEC Qualified: N; AEC Category: Q200
R146 R147 R155 R156 R295 R296 R374 = CMP-0026658-1: as R92 on sheet PROC111_System_Power_1
R148 R160 = CMP-0021602-3: RES, 18.2 k, 1%, 0.125 W, AEC-Q200 Grade 0, 0805; Manufacturer: Panasonic; Power_W: 125mW; TempCo: 100 ppm/C; Value_Code: 18k2; Value: 18.2k; EIA_Code: E96; SizeX_mm: 2; SizeY_mm: 1.25; SizeZ_mm: 1.45; Value2: 0.125W; SizeArea_mm2: 2.5; AEC Qualified: Y; AEC Category: Q200; AEC Grade: 0; SizeAreaWB_mm2: 6.75
R149 R150 R157 R158 = CMP-0026992-3: as R89 on sheet PROC111_System_Power_1
R151 = CMP-0026336-2: RES, 3.57 k, 1%, 0.063 W, AEC-Q200 Grade 0, 0402; Manufacturer: Vishay-Dale; Power_W: 63mW; TempCo: 100 ppm/C; Value_Code: 3k57; Value: 3.57k; EIA_Code: E96; SizeX_mm: 1; SizeY_mm: 0.5; SizeZ_mm: 0.6; Value2: 0.063W; AEC Qualified: Y; VDC_V: 50V; AEC Category: Q200; AEC Grade: 0
R152 = CMP-0026093-3: RES, 1.69 k, 1%, 0.063 W, AEC-Q200 Grade 0, 0402; Manufacturer: Vishay-Dale; Power_W: 63mW; TempCo: 100 ppm/C; Value_Code: 1k69; Value: 1.69k; EIA_Code: E96; SizeX_mm: 1; SizeY_mm: 0.5; SizeZ_mm: 0.6; Value2: 0.063W; AEC Qualified: Y; VDC_V: 50V; AEC Category: Q200; AEC Grade: 0
R153 = CMP-0026237-2: RES, 2.49 k, 1%, 0.063 W, AEC-Q200 Grade 0, 0402; Manufacturer: Vishay-Dale; Power_W: 63mW; TempCo: 100 ppm/C; Value_Code: 2k49; Value: 2.49k; EIA_Code: E96; SizeX_mm: 1; SizeY_mm: 0.5; SizeZ_mm: 0.6; Value2: 0.063W; AEC Qualified: Y; VDC_V: 50V; AEC Category: Q200; AEC Grade: 0
R154 R161 R163 R373 = CMP-0026414-2: RES, 4.99 k, 1%, 0.063 W, AEC-Q200 Grade 0, 0402; Manufacturer: Vishay-Dale; Power_W: 63mW; TempCo: 100 ppm/C; Value_Code: 4k99; Value: 4.99k; EIA_Code: E96; SizeX_mm: 1; SizeY_mm: 0.5; SizeZ_mm: 0.6; Value2: 0.063W; AEC Qualified: Y; VDC_V: 50V; AEC Category: Q200; AEC Grade: 0
R159 = CMP-0026097-2: RES, 1.87 k, 1%, 0.063 W, AEC-Q200 Grade 0, 0402; Manufacturer: Vishay-Dale; Power_W: 63mW; TempCo: 100 ppm/C; Value_Code: 1k87; Value: 1.87k; EIA_Code: E96; SizeX_mm: 1; SizeY_mm: 0.5; SizeZ_mm: 0.6; Value2: 0.063W; AEC Qualified: Y; VDC_V: 50V; AEC Category: Q200; AEC Grade: 0
R162 = CMP-0026028-3: RES, 15.4 k, 1%, 0.063 W, AEC-Q200 Grade 0, 0402; Manufacturer: Vishay-Dale; Power_W: 63mW; TempCo: 100 ppm/C; Value_Code: 15k4; Value: 15.4k; EIA_Code: E96; SizeX_mm: 1; SizeY_mm: 0.5; SizeZ_mm: 0.6; Value2: 0.063W; AEC Qualified: Y; VDC_V: 50V; AEC Category: Q200; AEC Grade: 0
R372 = CMP-0025960-3: RES, 10.5 k, 1%, 0.063 W, AEC-Q200 Grade 0, 0402; Manufacturer: Vishay-Dale; Power_W: 63mW; TempCo: 100 ppm/C; Value_Code: 10k5; Value: 10.5k; EIA_Code: E96; SizeX_mm: 1; SizeY_mm: 0.5; SizeZ_mm: 0.6; Value2: 0.063W; AEC Qualified: Y; VDC_V: 50V; AEC Category: Q200; AEC Grade: 0
R375 = CMP-0026659-2: RES, 100 k, 1%, 0.1 W, 0402; Manufacturer: Panasonic; U/M: EA; Value2: 0.1W; EIA_Code: E96; Value: 100k; SizeArea_mm2: 0.5; TempCo: 100 ppm/C; SizeZ_mm: 0.6; AEC Category: Q200; VDC_V: 50V; Power_W: 100mW; AEC Grade: 0; SizeX_mm: 1; AEC Qualified: Yes
TP8-TP17 = CMP-0078143-3: TEST POINT.  No entry in BOM.
U29 U32 = CMP-0089785-1: 3V to 17V, 3A Micro Noise (20µVRMS) and Micro Ripple (200µVPP) buck converter; Manufacturer: Texas Instruments; SizeZ_mm: 1mm; TJmax_C: +150°C; Output Type: AdjustableProgrammable; Switching Frequency: 1/2.2MHz; Max Duty Cycle: 55%; Number Of Outputs: 1; Nominal Supply Current: 5mA; AEC Qualified: No; Output Voltage: 0.8-5.5V; Standoff Height: 0mm
U30 U31 = CMP-0036365-5: Single Output LDO, 1.5A, Adj. (0.8 to 3.6V), Programmable Soft-Start, DRC0010J (VSON-10); Manufacturer: Texas Instruments; SizeArea_mm2: 9; Iq(Typ)(mA): 1; Vout Adj(Max)(V): 3.6; SizeY_mm: 3; Power Good: TRUE; AEC Category: Q200; Accuracy(%): 2; Rating: Catalog; Vdo(Typ)(mV): 60; Vin(Min)(V): 0.8; CompType: IC; Vin(Max)(V): 5.5; Iout(Max)(A): 1.5; AEC Qualified: N; SizeAreaWB_mm2: 16
U53 = CMP-0090914-1: Linear Voltage Regulator IC  1 Output  500mA SOT-23-5; Manufacturer: Texas Instruments; Output Type: AdjustableProgrammable; Number Of Outputs: 1; Standoff Height: 0mm; TJmax_C: +125°C; Accuracy Percentage: 0.7%; SizeZ_mm: 1.45mm; AEC Qualified: No; Dropout Voltage: 720mV; Max Supply Voltage: 6V; Min Supply Voltage: 1.5V; Output Voltage: 0.55-5.5V; Nominal Supply Current: 25uA

## Sheet PROC111_AM263x_1_Power.SchDoc
size 431 x 279 mm; Date: Not shown in title block; ApprovedBy: Not shown in title block; CheckedBy: Not shown in title block; Author: Not shown in title block; CompanyName: Not shown in title block; Engineer: Not shown in title block; Organization: Not shown in title block; Address1: Not shown in title block; Address2: Not shown in title block; Address3: Not shown in title block; Address4: Not shown in title block; DocumentNumber: 4; Revision: Use project parameter SCH_Rev; SheetNumber: 4; SheetTotal: 24; PageSetup: Record=PageOptions¦CenterHorizontal=True¦CenterVertical=True¦PrintScale=1.00¦XCorrection=1.00¦YCorrection=1.00¦PrintKind=0¦BorderSize=5000000¦LeftOffset=0¦BottomOffset=0¦Orientation=2¦PaperLength=1000¦PaperWidth=1000¦Scale=100¦PaperSource=15¦PrintQuality=600¦MediaType=1¦DitherType=10¦PaperKind=Letter¦PrintScaleMode=1
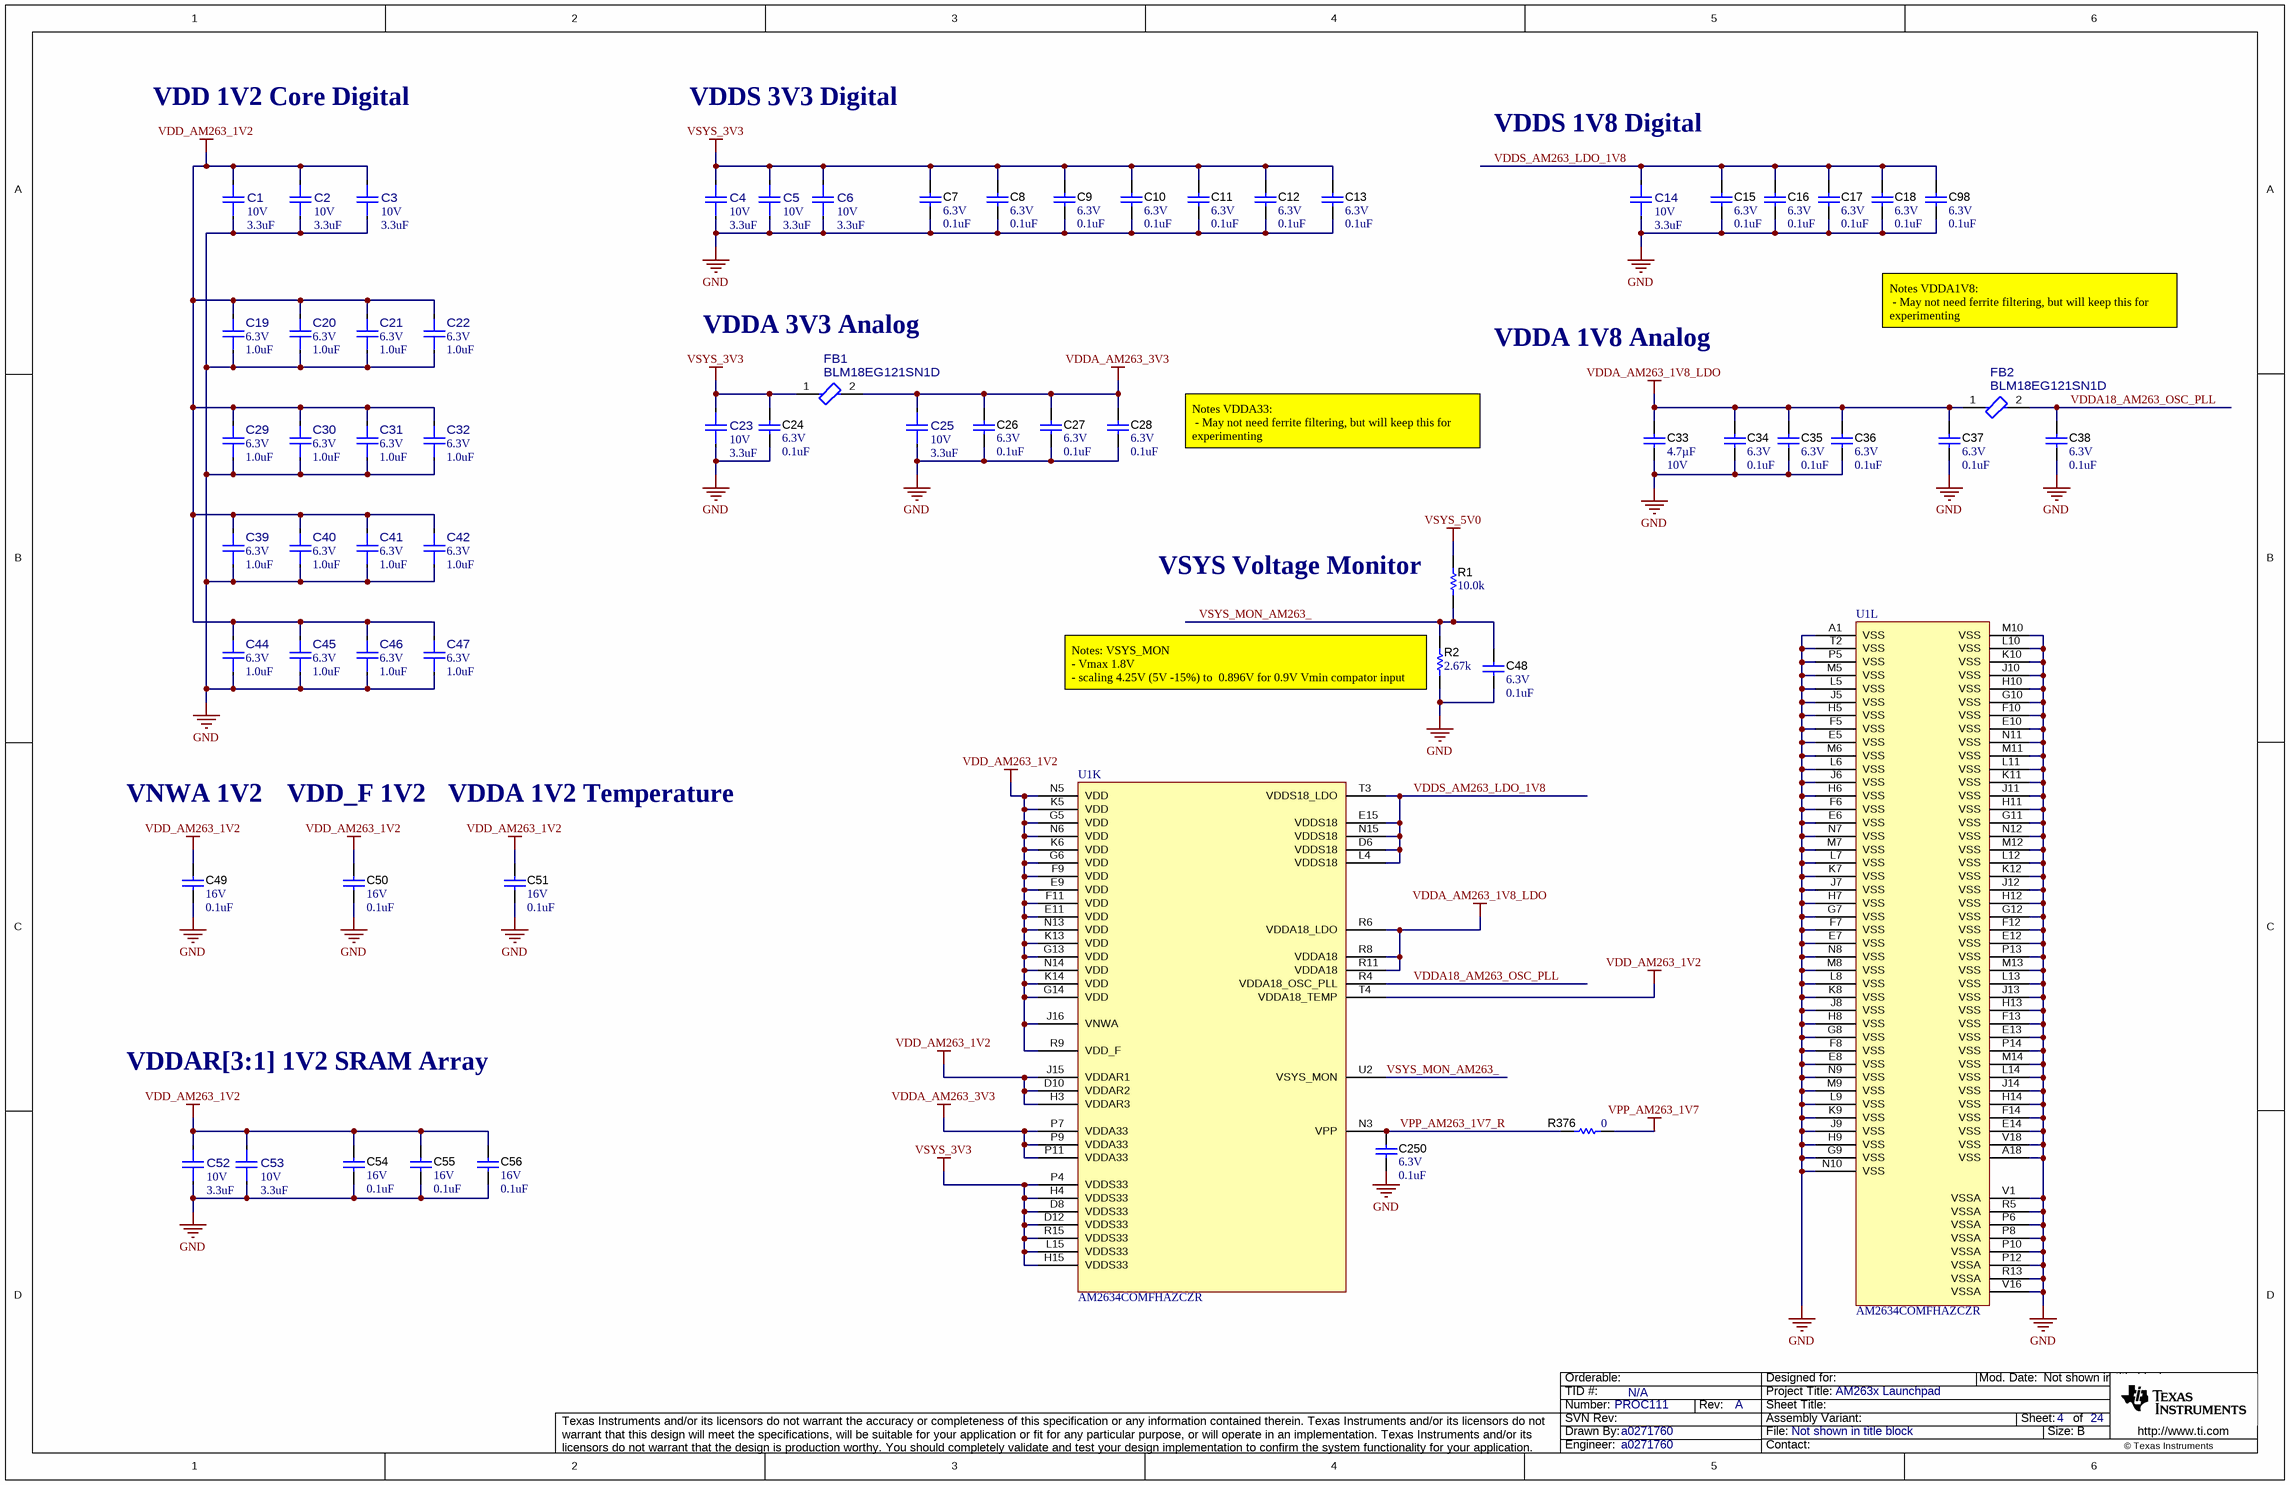
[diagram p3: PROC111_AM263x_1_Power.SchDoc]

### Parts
C1  VDC_V: 10V  ValueDisplayed: 3.3uF  [FP-CL10A335KP8NNNC_0603-MFG]  (hidden comment: CL10A335KP8NNNC)
C2  VDC_V: 10V  ValueDisplayed: 3.3uF  [FP-CL10A335KP8NNNC_0603-MFG]  (hidden comment: CL10A335KP8NNNC)
C3  VDC_V: 10V  ValueDisplayed: 3.3uF  [FP-CL10A335KP8NNNC_0603-MFG]  (hidden comment: CL10A335KP8NNNC)
C4  VDC_V: 10V  ValueDisplayed: 3.3uF  [FP-CL10A335KP8NNNC_0603-MFG]  (hidden comment: CL10A335KP8NNNC)
C5  VDC_V: 10V  ValueDisplayed: 3.3uF  [FP-CL10A335KP8NNNC_0603-MFG]  (hidden comment: CL10A335KP8NNNC)
C6  VDC_V: 10V  ValueDisplayed: 3.3uF  [FP-CL10A335KP8NNNC_0603-MFG]  (hidden comment: CL10A335KP8NNNC)
C7  VDC_V: 6.3V  ValueDisplayed: 0.1uF  [0402]  (hidden comment: GRM155R70J104KA01D)
C8  VDC_V: 6.3V  ValueDisplayed: 0.1uF  [0402]  (hidden comment: GRM155R70J104KA01D)
C9  VDC_V: 6.3V  ValueDisplayed: 0.1uF  [0402]  (hidden comment: GRM155R70J104KA01D)
C10  VDC_V: 6.3V  ValueDisplayed: 0.1uF  [0402]  (hidden comment: GRM155R70J104KA01D)
C11  VDC_V: 6.3V  ValueDisplayed: 0.1uF  [0402]  (hidden comment: GRM155R70J104KA01D)
C12  VDC_V: 6.3V  ValueDisplayed: 0.1uF  [0402]  (hidden comment: GRM155R70J104KA01D)
C13  VDC_V: 6.3V  ValueDisplayed: 0.1uF  [0402]  (hidden comment: GRM155R70J104KA01D)
C14  VDC_V: 10V  ValueDisplayed: 3.3uF  [FP-CL10A335KP8NNNC_0603-MFG]  (hidden comment: CL10A335KP8NNNC)
C15  VDC_V: 6.3V  ValueDisplayed: 0.1uF  [0402]  (hidden comment: GRM155R70J104KA01D)
C16  VDC_V: 6.3V  ValueDisplayed: 0.1uF  [0402]  (hidden comment: GRM155R70J104KA01D)
C17  VDC_V: 6.3V  ValueDisplayed: 0.1uF  [0402]  (hidden comment: GRM155R70J104KA01D)
C18  VDC_V: 6.3V  ValueDisplayed: 0.1uF  [0402]  (hidden comment: GRM155R70J104KA01D)
C19  VDC_V: 6.3V  ValueDisplayed: 1.0uF  [FP-GRM033C80J105ME05D_0201-MFG]  (hidden comment: GRM033C80J105ME05D)
C20  VDC_V: 6.3V  ValueDisplayed: 1.0uF  [FP-GRM033C80J105ME05D_0201-MFG]  (hidden comment: GRM033C80J105ME05D)
C21  VDC_V: 6.3V  ValueDisplayed: 1.0uF  [FP-GRM033C80J105ME05D_0201-MFG]  (hidden comment: GRM033C80J105ME05D)
C22  VDC_V: 6.3V  ValueDisplayed: 1.0uF  [FP-GRM033C80J105ME05D_0201-MFG]  (hidden comment: GRM033C80J105ME05D)
C23  VDC_V: 10V  ValueDisplayed: 3.3uF  [FP-CL10A335KP8NNNC_0603-MFG]  (hidden comment: CL10A335KP8NNNC)
C24  VDC_V: 6.3V  ValueDisplayed: 0.1uF  [0402]  (hidden comment: GRM155R70J104KA01D)
C25  VDC_V: 10V  ValueDisplayed: 3.3uF  [FP-CL10A335KP8NNNC_0603-MFG]  (hidden comment: CL10A335KP8NNNC)
C26  VDC_V: 6.3V  ValueDisplayed: 0.1uF  [0402]  (hidden comment: GRM155R70J104KA01D)
C27  VDC_V: 6.3V  ValueDisplayed: 0.1uF  [0402]  (hidden comment: GRM155R70J104KA01D)
C28  VDC_V: 6.3V  ValueDisplayed: 0.1uF  [0402]  (hidden comment: GRM155R70J104KA01D)
C29  VDC_V: 6.3V  ValueDisplayed: 1.0uF  [FP-GRM033C80J105ME05D_0201-MFG]  (hidden comment: GRM033C80J105ME05D)
C30  VDC_V: 6.3V  ValueDisplayed: 1.0uF  [FP-GRM033C80J105ME05D_0201-MFG]  (hidden comment: GRM033C80J105ME05D)
C31  VDC_V: 6.3V  ValueDisplayed: 1.0uF  [FP-GRM033C80J105ME05D_0201-MFG]  (hidden comment: GRM033C80J105ME05D)
C32  VDC_V: 6.3V  ValueDisplayed: 1.0uF  [FP-GRM033C80J105ME05D_0201-MFG]  (hidden comment: GRM033C80J105ME05D)
C33  Cap_F: 4.7µF  VDC_V: 10V  [0603]  (hidden comment: GRM188Z71A475ME15D)
C34  VDC_V: 6.3V  ValueDisplayed: 0.1uF  [0402]  (hidden comment: GRM155R70J104KA01D)
C35  VDC_V: 6.3V  ValueDisplayed: 0.1uF  [0402]  (hidden comment: GRM155R70J104KA01D)
C36  VDC_V: 6.3V  ValueDisplayed: 0.1uF  [0402]  (hidden comment: GRM155R70J104KA01D)
C37  VDC_V: 6.3V  ValueDisplayed: 0.1uF  [0402]  (hidden comment: GRM155R70J104KA01D)
C38  VDC_V: 6.3V  ValueDisplayed: 0.1uF  [0402]  (hidden comment: GRM155R70J104KA01D)
C39  VDC_V: 6.3V  ValueDisplayed: 1.0uF  [FP-GRM033C80J105ME05D_0201-MFG]  (hidden comment: GRM033C80J105ME05D)
C40  VDC_V: 6.3V  ValueDisplayed: 1.0uF  [FP-GRM033C80J105ME05D_0201-MFG]  (hidden comment: GRM033C80J105ME05D)
C41  VDC_V: 6.3V  ValueDisplayed: 1.0uF  [FP-GRM033C80J105ME05D_0201-MFG]  (hidden comment: GRM033C80J105ME05D)
C42  VDC_V: 6.3V  ValueDisplayed: 1.0uF  [FP-GRM033C80J105ME05D_0201-MFG]  (hidden comment: GRM033C80J105ME05D)
C44  VDC_V: 6.3V  ValueDisplayed: 1.0uF  [FP-GRM033C80J105ME05D_0201-MFG]  (hidden comment: GRM033C80J105ME05D)
C45  VDC_V: 6.3V  ValueDisplayed: 1.0uF  [FP-GRM033C80J105ME05D_0201-MFG]  (hidden comment: GRM033C80J105ME05D)
C46  VDC_V: 6.3V  ValueDisplayed: 1.0uF  [FP-GRM033C80J105ME05D_0201-MFG]  (hidden comment: GRM033C80J105ME05D)
C47  VDC_V: 6.3V  ValueDisplayed: 1.0uF  [FP-GRM033C80J105ME05D_0201-MFG]  (hidden comment: GRM033C80J105ME05D)
C48  VDC_V: 6.3V  ValueDisplayed: 0.1uF  [0402]  (hidden comment: GRM155R70J104KA01D)
C49  VDC_V: 16V  ValueDisplayed: 0.1uF  [0201]  (hidden comment: GRM033Z71C104KE14D)
C50  VDC_V: 16V  ValueDisplayed: 0.1uF  [0201]  (hidden comment: GRM033Z71C104KE14D)
C51  VDC_V: 16V  ValueDisplayed: 0.1uF  [0201]  (hidden comment: GRM033Z71C104KE14D)
C52  VDC_V: 10V  ValueDisplayed: 3.3uF  [FP-CL10A335KP8NNNC_0603-MFG]  (hidden comment: CL10A335KP8NNNC)
C53  VDC_V: 10V  ValueDisplayed: 3.3uF  [FP-CL10A335KP8NNNC_0603-MFG]  (hidden comment: CL10A335KP8NNNC)
C54  VDC_V: 16V  ValueDisplayed: 0.1uF  [0201]  (hidden comment: GRM033Z71C104KE14D)
C55  VDC_V: 16V  ValueDisplayed: 0.1uF  [0201]  (hidden comment: GRM033Z71C104KE14D)
C56  VDC_V: 16V  ValueDisplayed: 0.1uF  [0201]  (hidden comment: GRM033Z71C104KE14D)
C98  VDC_V: 6.3V  ValueDisplayed: 0.1uF  [0402S]  (hidden comment: GRM155R70J104KA01D)
C250  VDC_V: 6.3V  ValueDisplayed: 0.1uF  [0402]  (hidden comment: GRM155R70J104KA01D)
FB1  BLM18EG121SN1D  [FP-BLM18EG121SN1D_0603-MFG]
FB2  BLM18EG121SN1D  [FP-BLM18EG121SN1D_0603-MFG]
R1  ValueDisplayed: 10.0k  [0402]  (hidden comment: ERJ-2RKF1002X)
R2  ValueDisplayed: 2.67k  [0402]  (hidden comment: CRCW04022K67FKED)
R376  value 0  [0402S]  (hidden comment: ERJ-2GE0R00X)
U1  AM2634COMFHAZCZR  [ZCZ (S-PBGA-N324)]  (parts K,L of 13)

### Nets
GND: C1.1 C2.1 C3.1 C4.1 C5.1 C6.1 C7.2 C8.2 C9.2 C10.2 C11.2 C12.2 C13.2 C14.1 C15.2 C16.2 C17.2 C18.2 C19.1 C20.1 C21.1 C22.1 C23.1 C24.2 C25.1 C26.2 C27.2 C28.2 C29.1 C30.1 C31.1 C32.1 C33.2 C34.2 C35.2 C36.2 C37.2 C38.2 C39.1 C40.1 C41.1 C42.1 C44.1 C45.1 C46.1 C47.1 C48.2 C49.2 C50.2 C51.2 C52.1 C53.1 C54.2 C55.2 C56.2 C98.2 C250.2 R2.1 U1.A1(VSS) U1.A18(VSS) U1.E5(VSS) U1.E6(VSS) U1.E7(VSS) U1.E8(VSS) U1.E10(VSS) U1.E12(VSS) U1.E13(VSS) U1.E14(VSS) U1.F5(VSS) U1.F6(VSS) U1.F7(VSS) U1.F8(VSS) U1.F10(VSS) U1.F12(VSS) U1.F13(VSS) U1.F14(VSS) U1.G7(VSS) U1.G8(VSS) U1.G9(VSS) U1.G10(VSS) U1.G11(VSS) U1.G12(VSS) U1.H5(VSS) U1.H6(VSS) U1.H7(VSS) U1.H8(VSS) U1.H9(VSS) U1.H10(VSS) U1.H11(VSS) U1.H12(VSS) U1.H13(VSS) U1.H14(VSS) U1.J5(VSS) U1.J6(VSS) U1.J7(VSS) U1.J8(VSS) U1.J9(VSS) U1.J10(VSS) U1.J11(VSS) U1.J12(VSS) U1.J13(VSS) U1.J14(VSS) U1.K7(VSS) U1.K8(VSS) U1.K9(VSS) U1.K10(VSS) U1.K11(VSS) U1.K12(VSS) U1.L5(VSS) U1.L6(VSS) U1.L7(VSS) U1.L8(VSS) U1.L9(VSS) U1.L10(VSS) U1.L11(VSS) U1.L12(VSS) U1.L13(VSS) U1.L14(VSS) U1.M5(VSS) U1.M6(VSS) U1.M7(VSS) U1.M8(VSS) U1.M9(VSS) U1.M10(VSS) U1.M11(VSS) U1.M12(VSS) U1.M13(VSS) U1.M14(VSS) U1.N7(VSS) U1.N8(VSS) U1.N9(VSS) U1.N10(VSS) U1.N11(VSS) U1.N12(VSS) U1.P5(VSS) U1.P6(VSSA) U1.P8(VSSA) U1.P10(VSSA) U1.P12(VSSA) U1.P13(VSS) U1.P14(VSS) U1.R5(VSSA) U1.R13(VSSA) U1.T2(VSS) U1.V1(VSSA) U1.V16(VSSA) U1.V18(VSS)
VDD_AM263_1V2: C1.2 C2.2 C3.2 C19.2 C20.2 C21.2 C22.2 C29.2 C30.2 C31.2 C32.2 C39.2 C40.2 C41.2 C42.2 C44.2 C45.2 C46.2 C47.2 C49.1 C50.1 C51.1 C52.2 C53.2 C54.1 C55.1 C56.1 U1.D10(VDDAR2) U1.E9(VDD) U1.E11(VDD) U1.F9(VDD) U1.F11(VDD) U1.G5(VDD) U1.G6(VDD) U1.G13(VDD) U1.G14(VDD) U1.H3(VDDAR3) U1.J15(VDDAR1) U1.J16(VNWA) U1.K5(VDD) U1.K6(VDD) U1.K13(VDD) U1.K14(VDD) U1.N5(VDD) U1.N6(VDD) U1.N13(VDD) U1.N14(VDD) U1.R9(VDD_F) U1.T4(VDDA18_TEMP)
VDDA_AM263_1V8_LDO: C33.1 C34.1 C35.1 C36.1 C37.1 FB2.1 U1.R6(VDDA18_LDO) U1.R8(VDDA18) U1.R11(VDDA18)
VDDA_AM263_3V3: C25.2 C26.1 C27.1 C28.1 FB1.2 U1.P7(VDDA33) U1.P9(VDDA33) U1.P11(VDDA33)
VPP_AM263_1V7: R376.2
VSYS_3V3: C4.2 C5.2 C6.2 C7.1 C8.1 C9.1 C10.1 C11.1 C12.1 C13.1 C23.2 C24.1 FB1.1 U1.D8(VDDS33) U1.D12(VDDS33) U1.H4(VDDS33) U1.H15(VDDS33) U1.L15(VDDS33) U1.P4(VDDS33) U1.R15(VDDS33)
VSYS_5V0: R1.2
VDDA18_AM263_OSC_PLL: C38.1 FB2.2 U1.R4(VDDA18_OSC_PLL)
VDDS_AM263_LDO_1V8: C14.2 C15.1 C16.1 C17.1 C18.1 C98.1 U1.D6(VDDS18) U1.E15(VDDS18) U1.L4(VDDS18) U1.N15(VDDS18) U1.T3(VDDS18_LDO)
VPP_AM263_1V7_R: C250.1 R376.1 U1.N3(VPP)
VSYS_MON_AM263_: C48.1 R1.1 R2.2 U1.U2(VSYS_MON)

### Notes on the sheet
- VDD 1V2 Core Digital
- VDDS 3V3 Digital
- VDDS 1V8 Digital
- VDDA 3V3 Analog
- VDDA 1V8 Analog
- Notes VDDA1V8:
  - May not need ferrite filtering, but will keep this for experimenting
- Notes VDDA33:
  - May not need ferrite filtering, but will keep this for experimenting
- (near R1) VSYS Voltage Monitor
- (near R2) Notes: VSYS_MON
  - Vmax 1.8V
  - scaling 4.25V (5V -15%) to  0.896V for 0.9V Vmin compator input
- VNWA 1V2
- VDD_F 1V2
- VDDA 1V2 Temperature
- VDDAR[3:1] 1V2 SRAM Array

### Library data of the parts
C1-C6 C14 C23 C25 C52 C53 = CMP-0042976-1: Cap Ceramic 3.3uF 10V X5R ±10% Pad SMD 0603 +85°C T/R; Manufacturer: Samsung; TempCo: 15%; Value: 3.3µF; SizeZ_mm: 0.9mm; AEC Qualified: No
C7-C13 C15-C18 C24 C26-C28 C34-C38 C48 C250 = CMP-0006623-2: as C165 on sheet PROC111_System_Power_2
C19-C22 C29-C32 C39-C42 C44-C47 = CMP-0093721-1: Chip Multilayer Ceramic Capacitors for General Purpose, 0201, 1.0uF, X6S, 22%, 20%, 6.3V; Manufacturer: Murata; Cap_F: 1µF; Value: 1µF; AEC Qualified: No; SizeZ_mm: 0.39mm
C33 = CMP-0007498-4: CAP, CERM, 4.7 uF, 10 V, +/- 20%, X7R, 0603; Manufacturer: MuRata; TaMin_C: -55°C; Polarized: N; SizeAreaWB_mm2: 4.68; Value1: Unknown; U/M: EA; Value: 4.7uF; TaMax_C: 125°C; SizeZ_mm: 1; SizeX_mm: 1.6; SizeY_mm: 0.8; SizeArea_mm2: 1.28; AEC Category: Q200
C49-C51 C54-C56 = CMP-0064970-1: CAP, CERM, 0.1 uF, 16 V,+/- 10%, X7R, 0201; Manufacturer: MuRata; TaMin_C: -55°C; Polarized: N; SizeAreaWB_mm2: 2.08; Value1: Unknown; U/M: EA; Value: 0.1uF; TaMax_C: 125°C; SizeZ_mm: 0.26; SizeX_mm: 0.6; SizeY_mm: 0.3; SizeArea_mm2: 0.18; Cap_F: 100nF; AEC Category: Q200
C98 = CMP-0006623-2: CAP, CERM, 0.1 uF, 6.3 V, +/- 10%, X7R, 0402; Manufacturer: MuRata; TaMin_C: -55°C; Polarized: N; SizeAreaWB_mm2: 3; Value1: Unknown; U/M: EA; Value: 0.1uF; TaMax_C: 125°C; SizeZ_mm: 0.6; SizeX_mm: 1; SizeY_mm: 0.5; Cap_Case: 0402; Cap_F: 100nF; AEC Category: Q200
FB1 FB2 = CMP-0089199-1: 120 Ohms @ 100MHz 1  Ferrite Bead 0603 (1608 Metric) 2A 40mOhm; Manufacturer: Murata; DCR_ohm: 60m; AEC Qualified: No; Tolerance_%: 25%; SizeZ_mm: 0.95mm; Impedance At Frequency: 120Ω @ 100MHz
R1 = CMP-0026658-1: as R92 on sheet PROC111_System_Power_1
R2 = CMP-0026240-2: RES, 2.67 k, 1%, 0.063 W, AEC-Q200 Grade 0, 0402; Manufacturer: Vishay-Dale; Power_W: 63mW; TempCo: 100 ppm/C; Value_Code: 2k67; Value: 2.67k; EIA_Code: E96; SizeX_mm: 1; SizeY_mm: 0.5; SizeZ_mm: 0.6; Value2: 0.063W; AEC Qualified: Y; VDC_V: 50V; AEC Category: Q200; AEC Grade: 0
R376 = CMP-0026992-3: RES, 0, 5%, 0.1 W, AEC-Q200 Grade 0, 0402; Manufacturer: Panasonic; Power_W: 100mW; TempCo: 600 ppm/C; Value_Code: 0000; EIA_Code: E24; SizeX_mm: 1; SizeY_mm: 0.5; SizeZ_mm: 0.6; Value2: 0.1W; AEC Qualified: Y; VDC_V: 50V; AEC Category: Q200; SizeAreaWB_mm2: 3
U1 = AM263x: Sitara AM263x MCU; Manufacturer: Texas Instruments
